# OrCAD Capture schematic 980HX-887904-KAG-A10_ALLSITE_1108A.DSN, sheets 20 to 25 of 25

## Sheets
20 T04.GROUP8.U4: size D
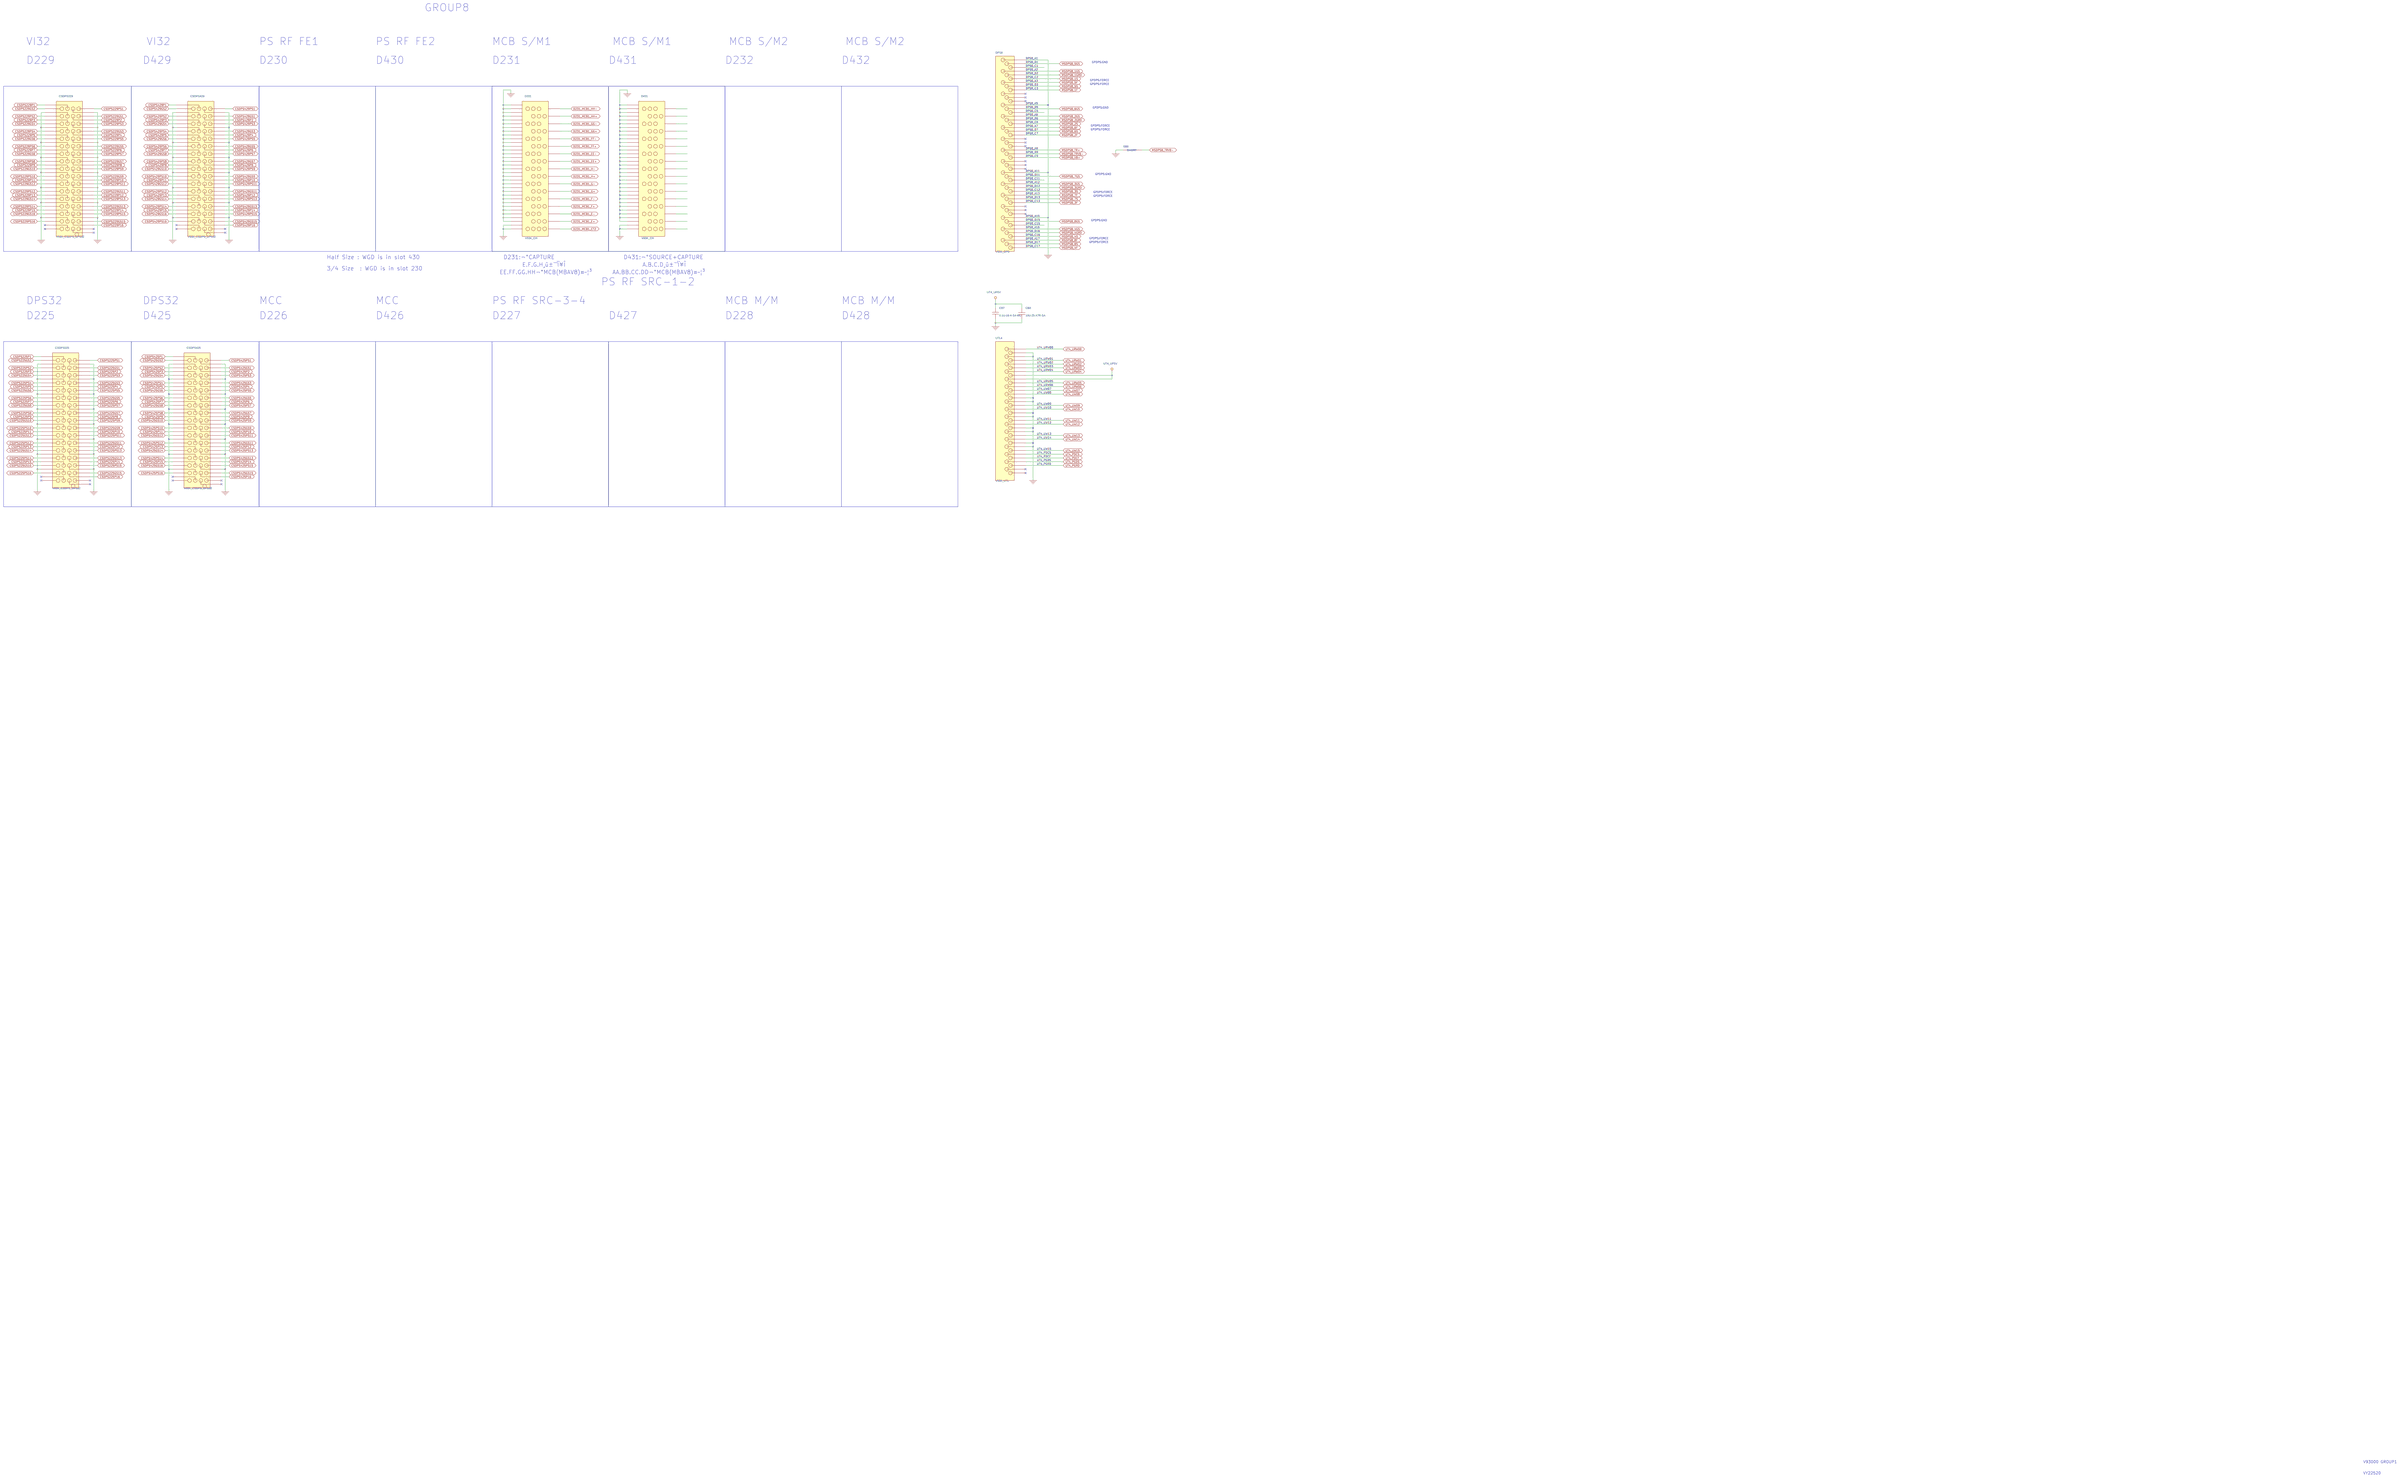
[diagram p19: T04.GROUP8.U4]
21 T05.GROUP4.U5: size D
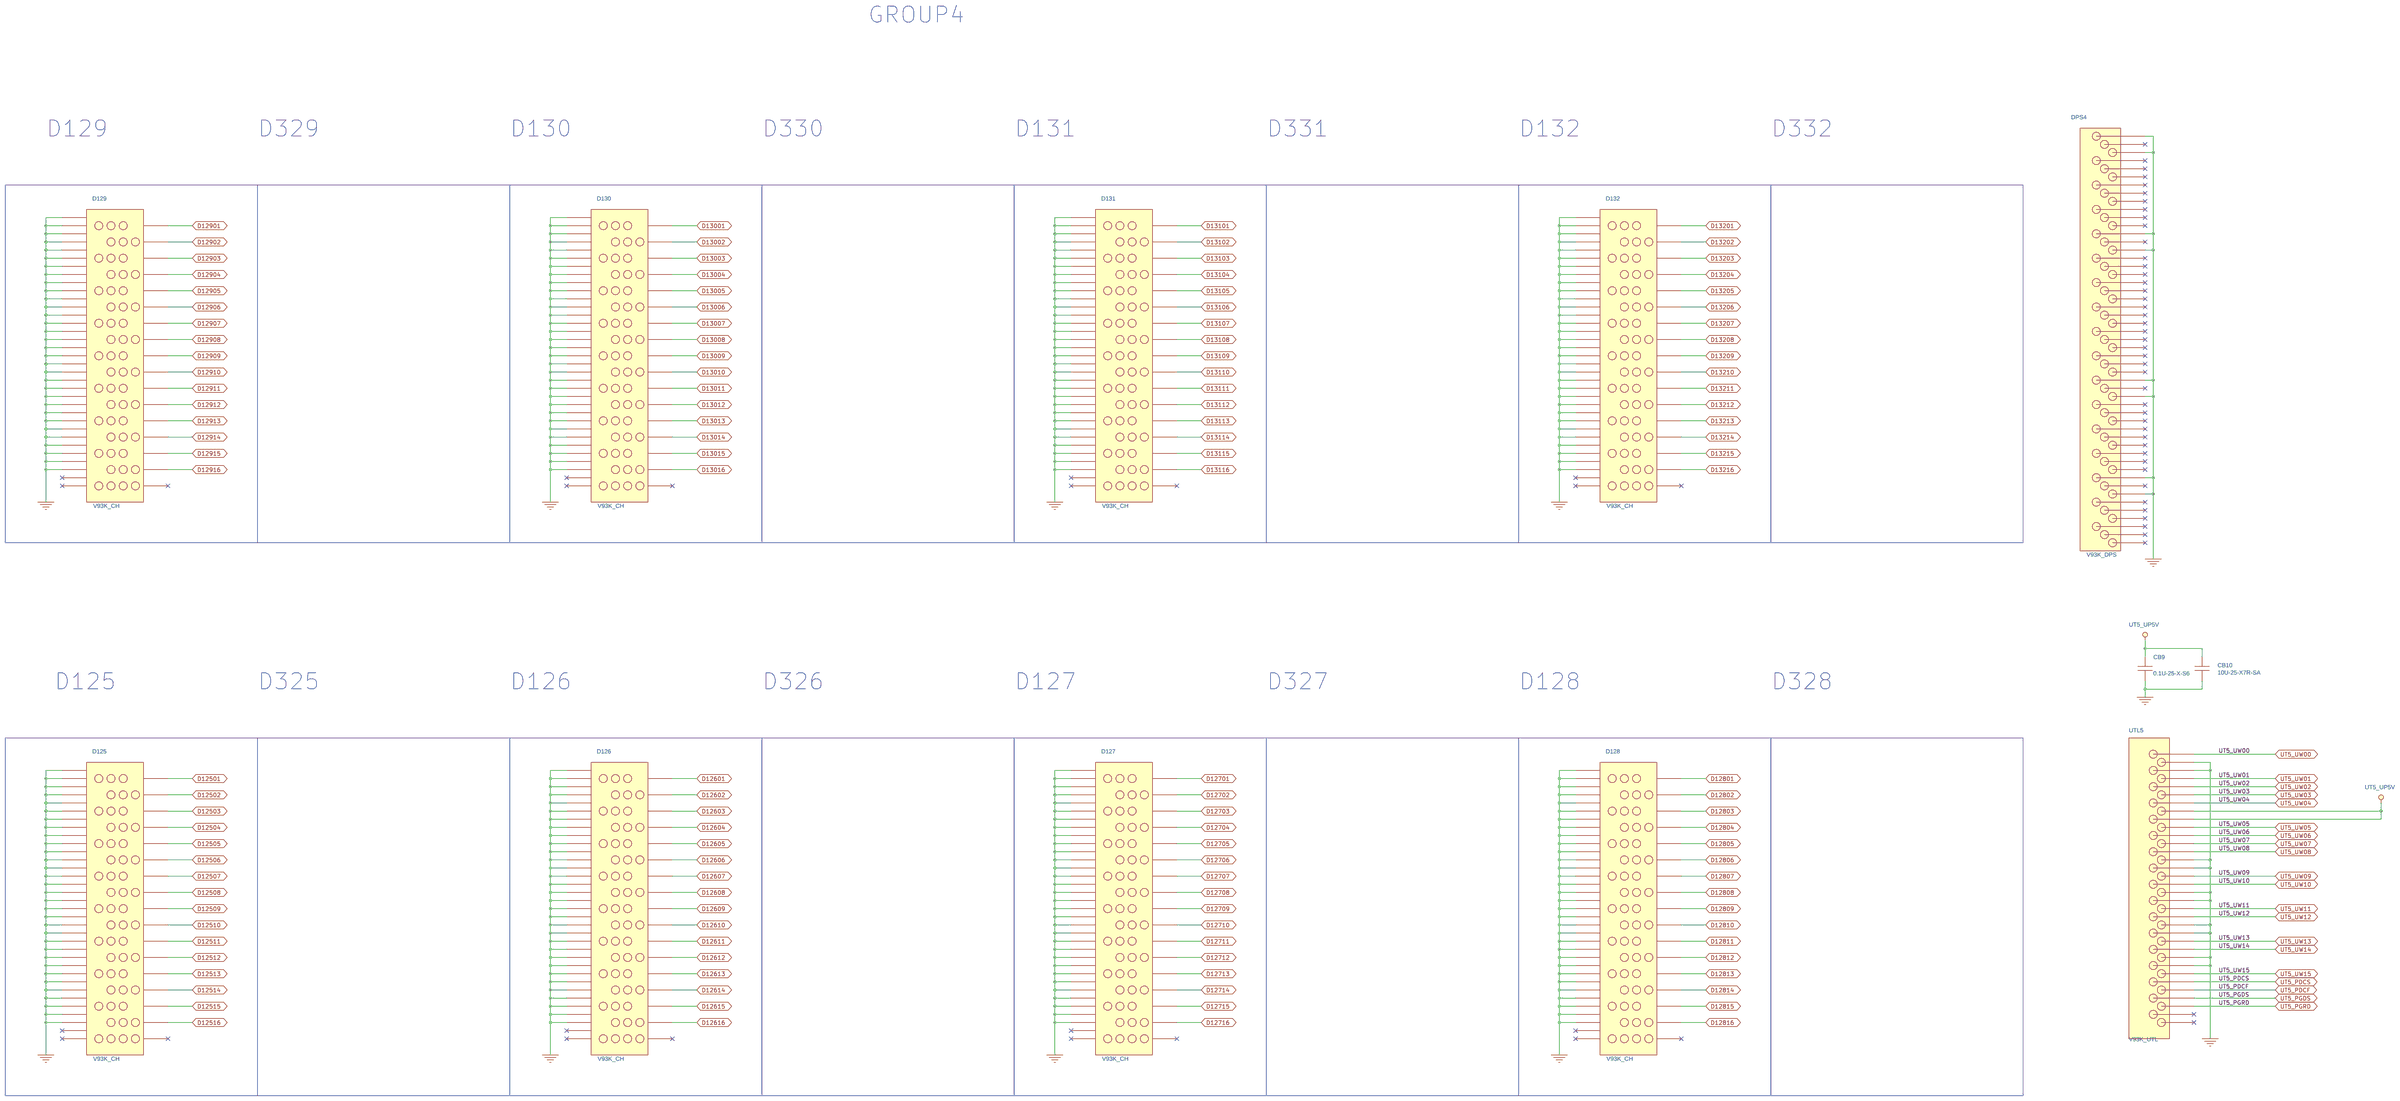
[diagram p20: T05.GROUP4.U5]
22 T06.GROUP5.U6: size D
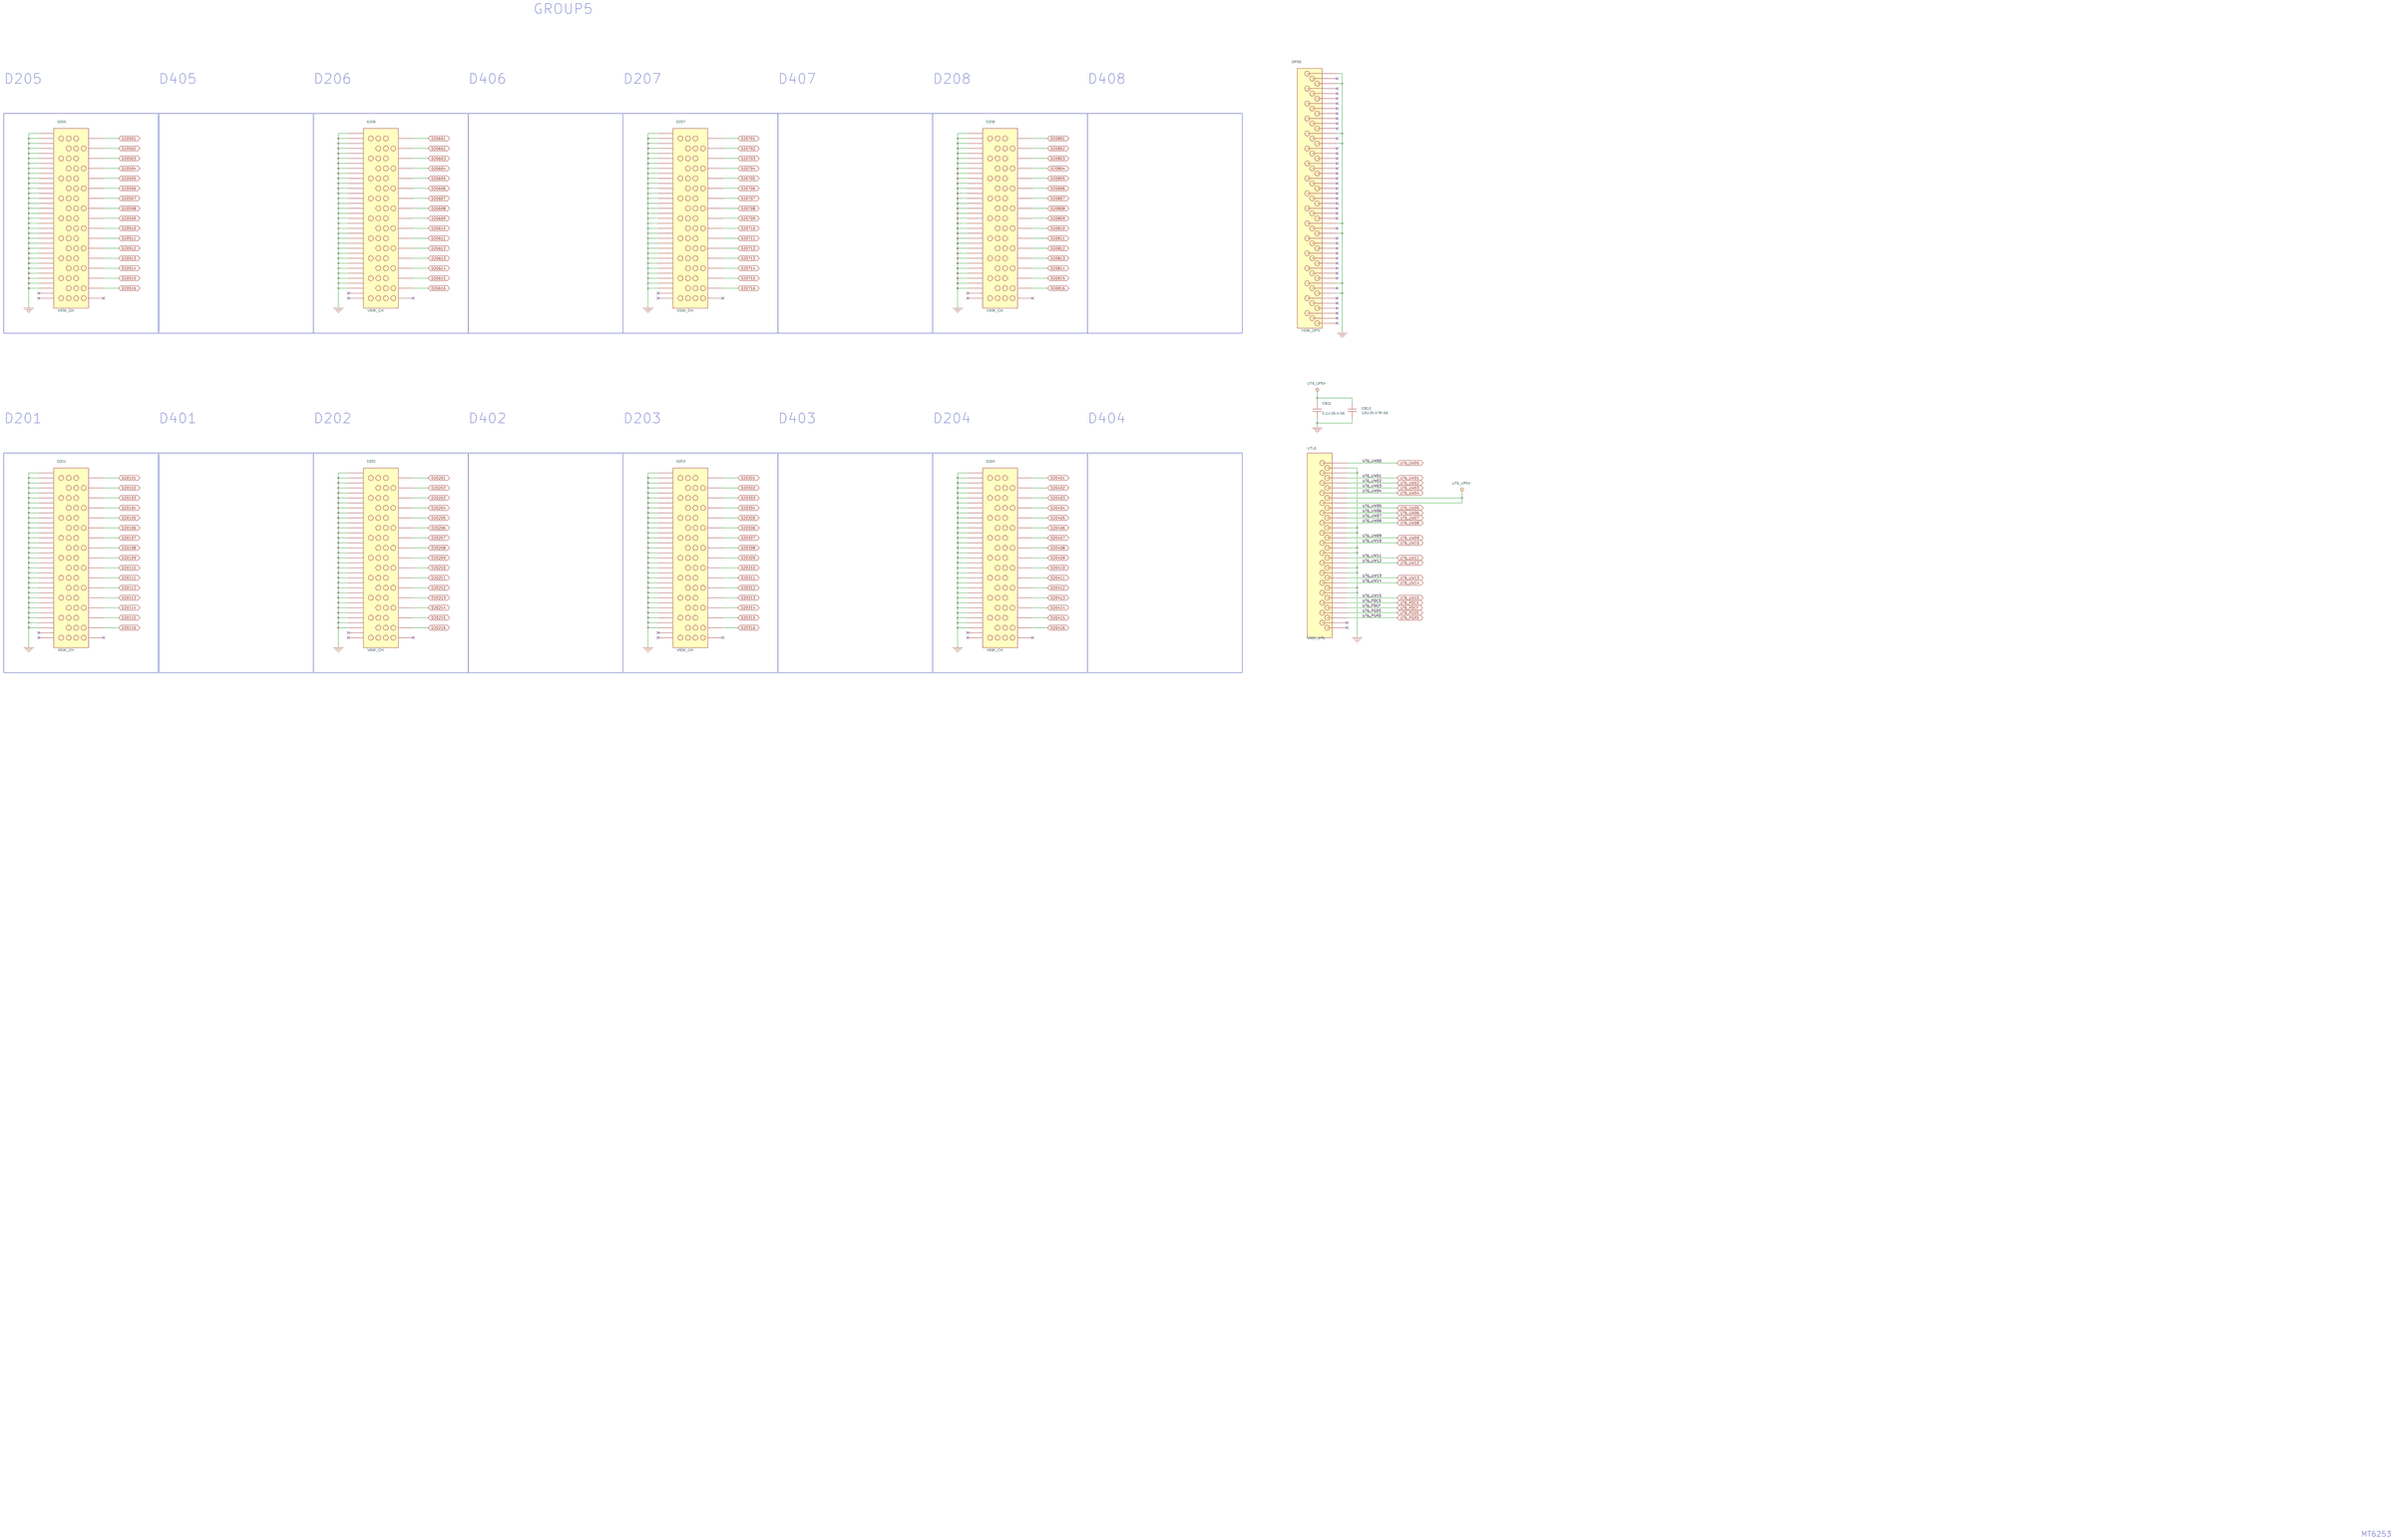
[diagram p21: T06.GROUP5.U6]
23 T07.GROUP6.U7: size D
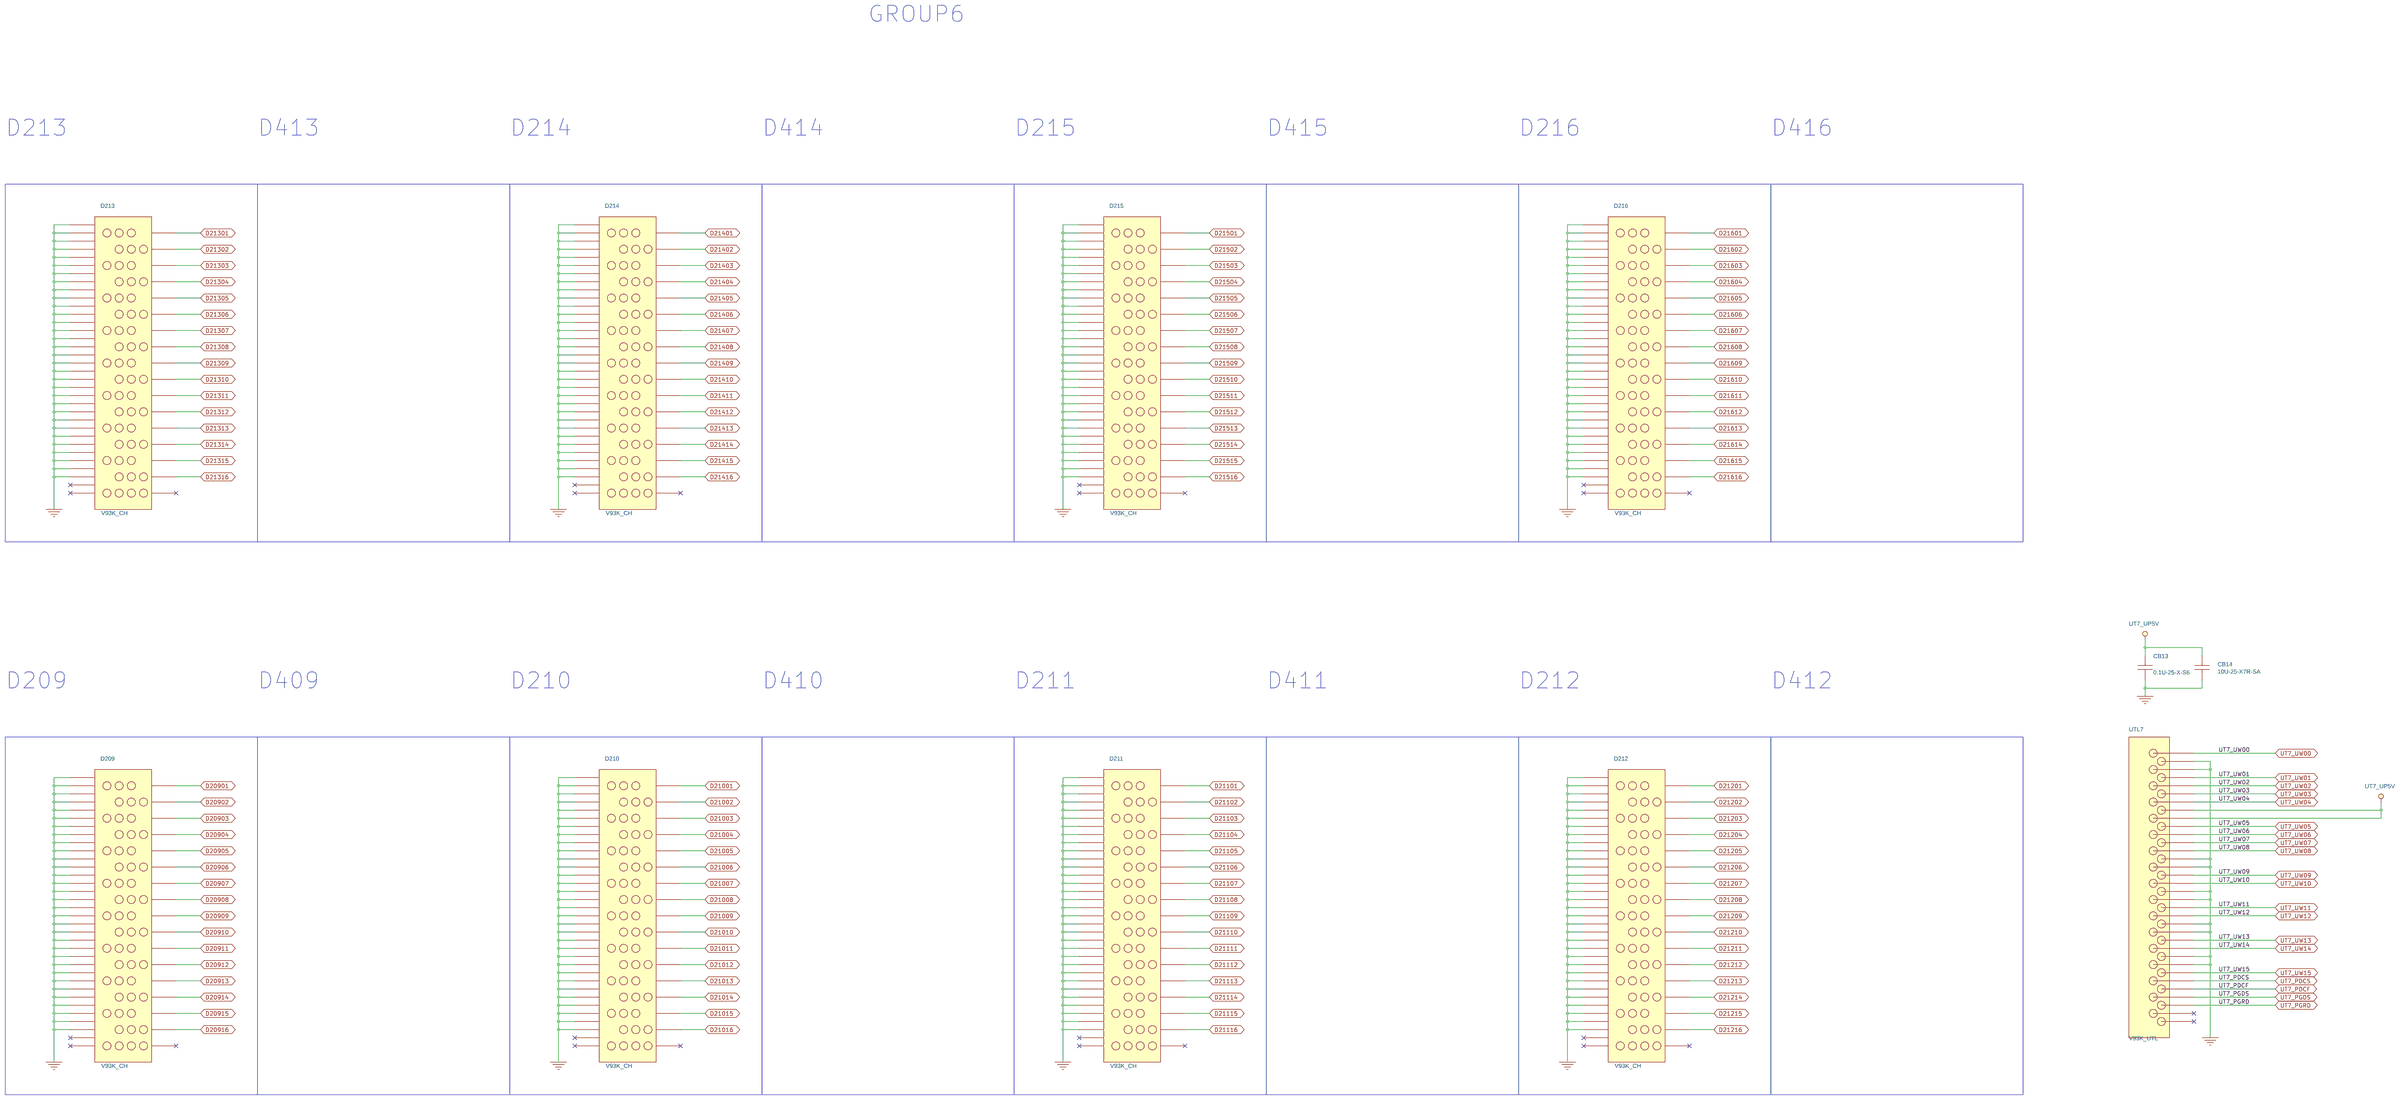
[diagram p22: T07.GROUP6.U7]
24 T08.GROUP7.U8: size D
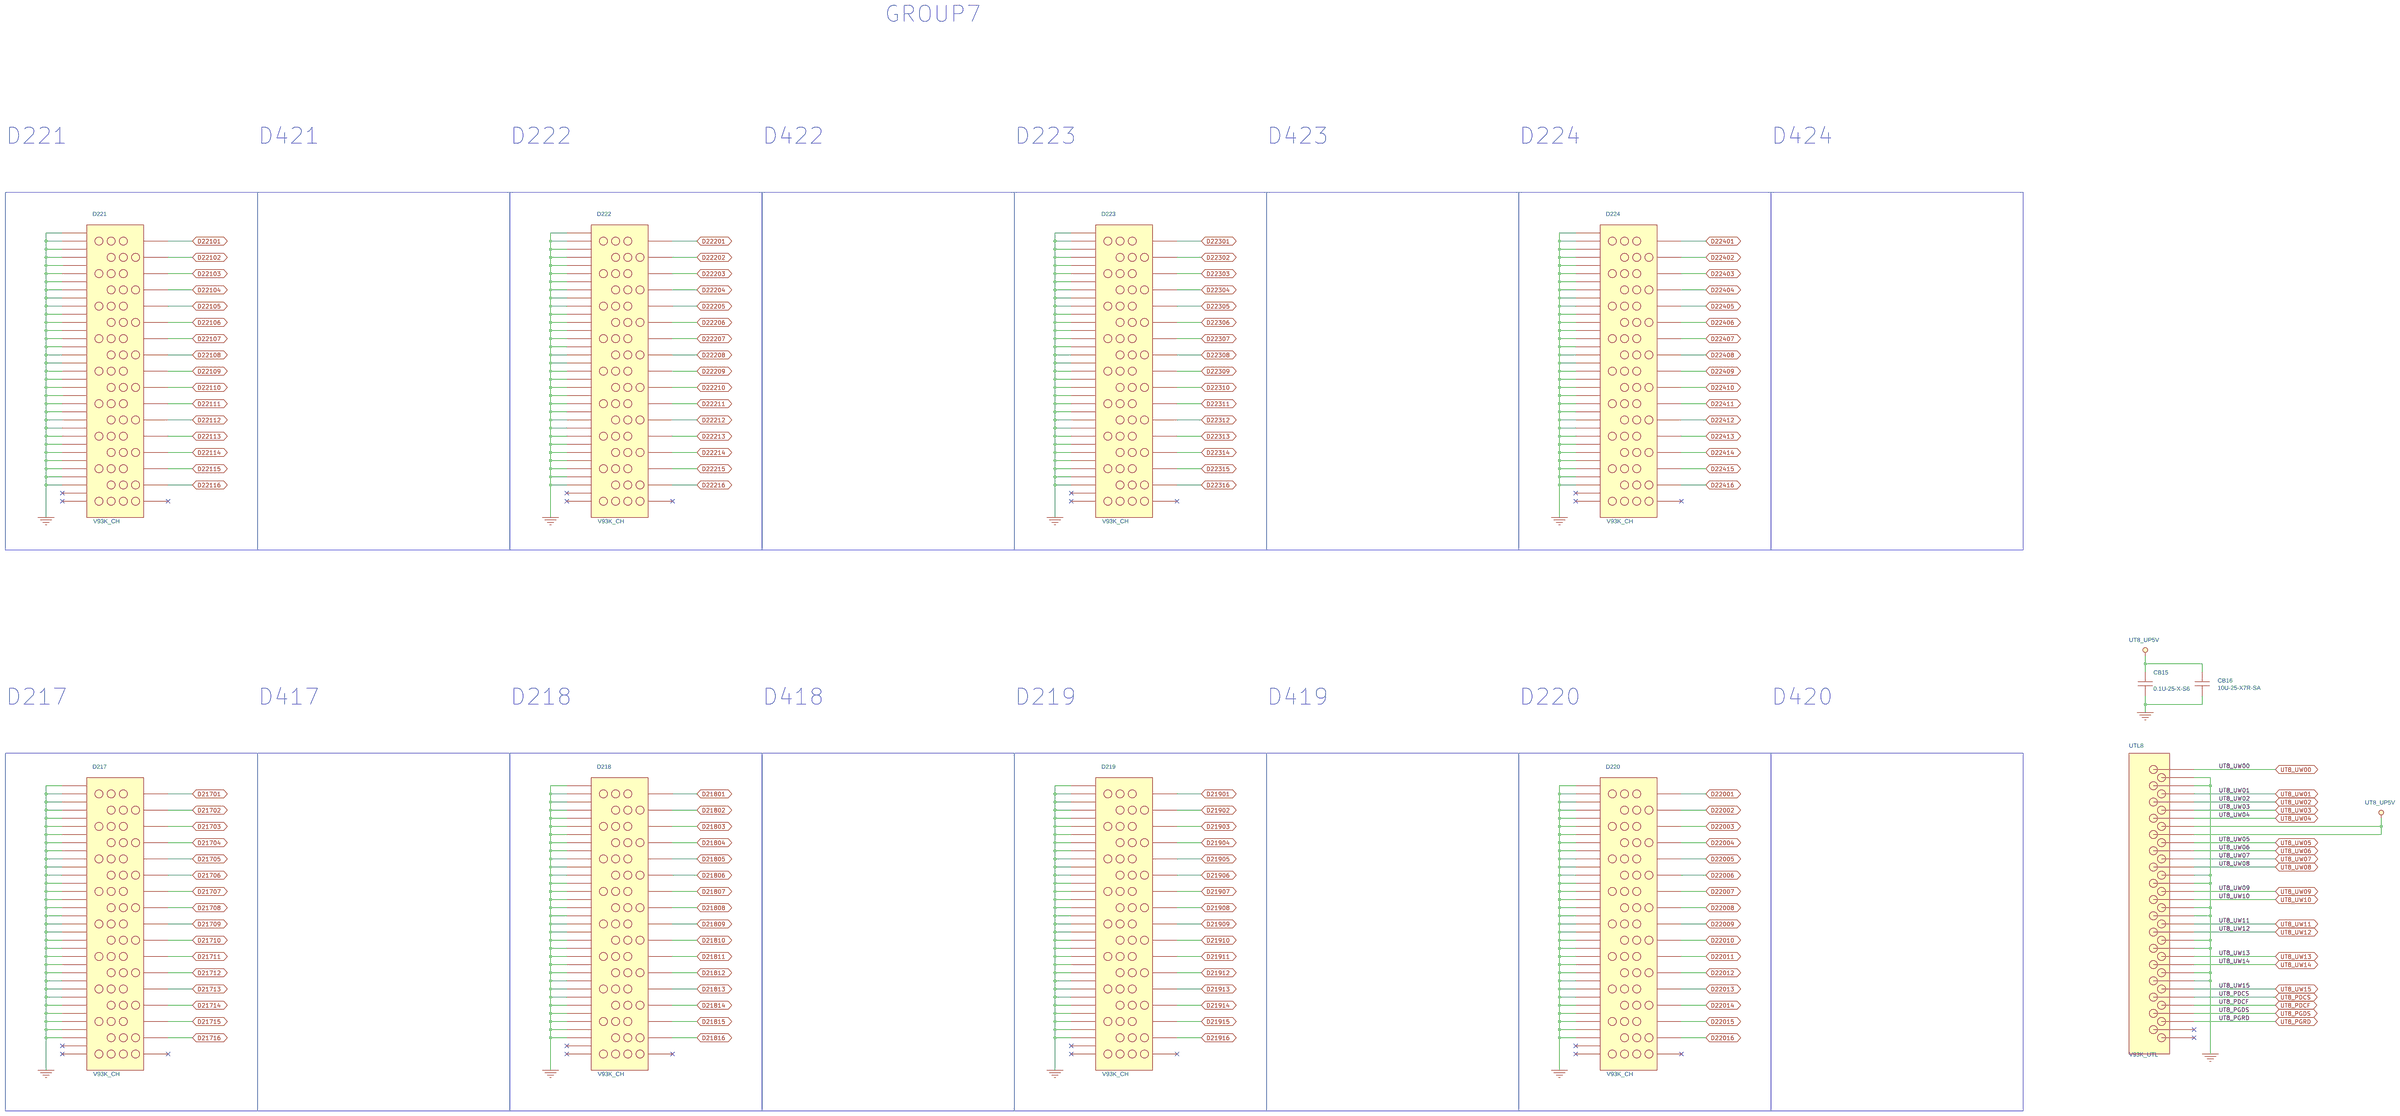
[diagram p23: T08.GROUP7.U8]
25 X01-ASSIGN RULE: size A3
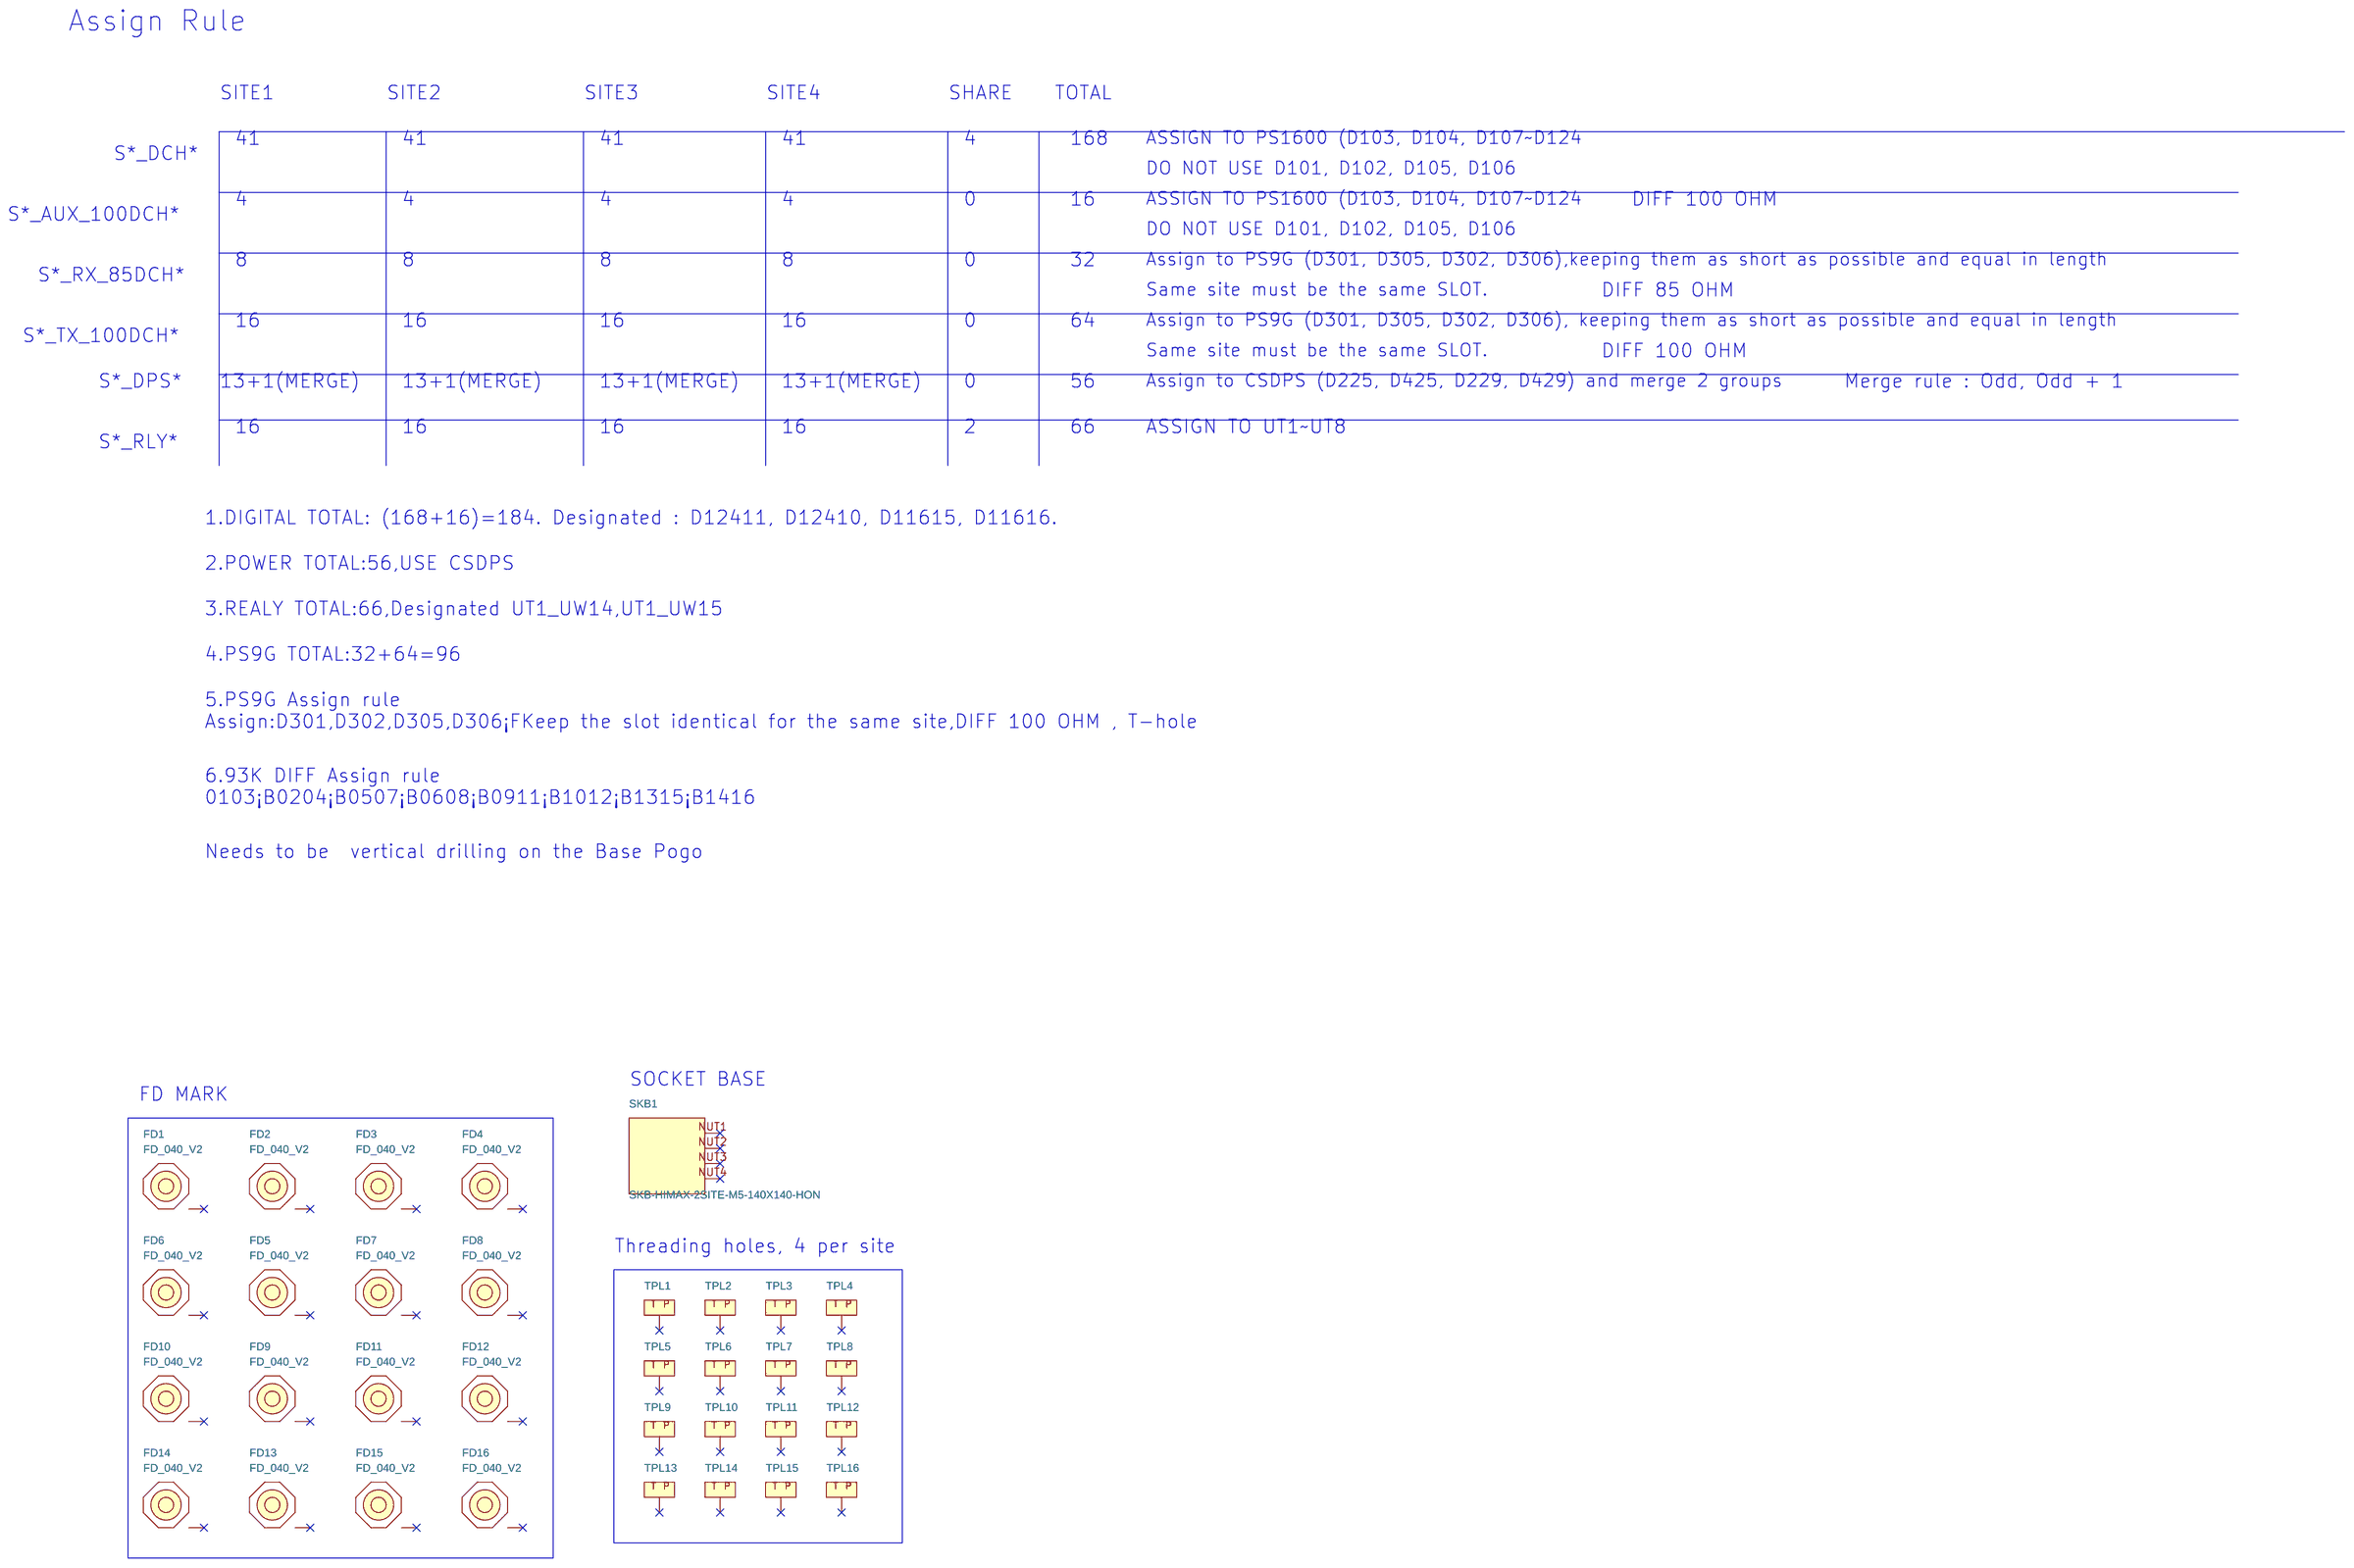
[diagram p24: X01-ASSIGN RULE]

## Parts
sheet T04.GROUP8.U4
CB7  0.1U-16-X-S4-MU  [C0402]
CB8  10U-25-X7R-SA  [C1206]
CSDPS225  V93K_CSDPS_DPS32  [PG_VG93K_PF_DPS32_G8D225]
CSDPS229  V93K_CSDPS_DPS32  [PG_VG93K_PF_DPS32_G8D229]
CSDPS425  V93K_CSDPS_DPS32  [PG_VG93K_PF_DPS32_G8D425]
CSDPS429  V93K_CSDPS_DPS32  [PG_VG93K_PF_DPS32_G8D429]
D231  V93K_CH  [PG_VG93K_F_G8D231]
D431  V93K_CH  [PG_VG93K_F_G8D431]
DPS8  V93K_DPS  [PG_VG93K_F_G8DPS8]
SB8  SHORT  [DEFAULT_SHORT_SMALL]
UTL4  V93K_UTL  [PG_VG93K_F_G8UTI4]
sheet T05.GROUP4.U5
CB9  0.1U-25-X-S6  [C0603]
CB10  10U-25-X7R-SA  [C1206]
D125  V93K_CH  [PG_VG93K_F_G4D125]
D126  V93K_CH  [PG_VG93K_F_G4D126]
D127  V93K_CH  [PG_VG93K_F_G4D127]
D128  V93K_CH  [PG_VG93K_F_G4D128]
D129  V93K_CH  [PG_VG93K_F_G4D129]
D130  V93K_CH  [PG_VG93K_F_G4D130]
D131  V93K_CH  [PG_VG93K_F_G4D131]
D132  V93K_CH  [PG_VG93K_F_G4D132]
DPS4  V93K_DPS  [PG_VG93K_F_G4DPS4]
UTL5  V93K_UTL  [PG_VG93K_F_G4UTI5]
sheet T06.GROUP5.U6
CB11  0.1U-25-X-S6  [C0603]
CB12  10U-25-X7R-SA  [C1206]
D201  V93K_CH  [PG_VG93K_F_G5D201]
D202  V93K_CH  [PG_VG93K_F_G5D202]
D203  V93K_CH  [PG_VG93K_F_G5D203]
D204  V93K_CH  [PG_VG93K_F_G5D204]
D205  V93K_CH  [PG_VG93K_F_G5D205]
D206  V93K_CH  [PG_VG93K_F_G5D206]
D207  V93K_CH  [PG_VG93K_F_G5D207]
D208  V93K_CH  [PG_VG93K_F_G5D208]
DPS5  V93K_DPS  [PG_VG93K_F_G5DPS5]
UTL6  V93K_UTL  [PG_VG93K_F_G5UTI6]
sheet T07.GROUP6.U7
CB13  0.1U-25-X-S6  [C0603]
CB14  10U-25-X7R-SA  [C1206]
D209  V93K_CH  [PG_VG93K_F_G6D209]
D210  V93K_CH  [PG_VG93K_F_G6D210]
D211  V93K_CH  [PG_VG93K_F_G6D211]
D212  V93K_CH  [PG_VG93K_F_G6D212]
D213  V93K_CH  [PG_VG93K_F_G6D213]
D214  V93K_CH  [PG_VG93K_F_G6D214]
D215  V93K_CH  [PG_VG93K_F_G6D215]
D216  V93K_CH  [PG_VG93K_F_G6D216]
UTL7  V93K_UTL  [PG_VG93K_F_G6UTI7]
sheet T08.GROUP7.U8
CB15  0.1U-25-X-S6  [C0603]
CB16  10U-25-X7R-SA  [C1206]
D217  V93K_CH  [PG_VG93K_F_G7D217]
D218  V93K_CH  [PG_VG93K_F_G7D218]
D219  V93K_CH  [PG_VG93K_F_G7D219]
D220  V93K_CH  [PG_VG93K_F_G7D220]
D221  V93K_CH  [PG_VG93K_F_G7D221]
D222  V93K_CH  [PG_VG93K_F_G7D222]
D223  V93K_CH  [PG_VG93K_F_G7D223]
D224  V93K_CH  [PG_VG93K_F_G7D224]
UTL8  V93K_UTL  [PG_VG93K_F_G7UTI8]
sheet X01-ASSIGN RULE
FD1  FD_040_V2  [FD_040_V2]
FD2  FD_040_V2  [FD_040_V2]
FD3  FD_040_V2  [FD_040_V2]
FD4  FD_040_V2  [FD_040_V2]
FD5  FD_040_V2  [FD_040_V2]
FD6  FD_040_V2  [FD_040_V2]
FD7  FD_040_V2  [FD_040_V2]
FD8  FD_040_V2  [FD_040_V2]
FD9  FD_040_V2  [FD_040_V2]
FD10  FD_040_V2  [FD_040_V2]
FD11  FD_040_V2  [FD_040_V2]
FD12  FD_040_V2  [FD_040_V2]
FD13  FD_040_V2  [FD_040_V2]
FD14  FD_040_V2  [FD_040_V2]
FD15  FD_040_V2  [FD_040_V2]
FD16  FD_040_V2  [FD_040_V2]
SKB1  SKB-HIMAX-2SITE-M5-140X140-HON  [SOCKETBASE_294X213_888003]
TPL1  TPL01  [TPL_040_014_TB]
TPL2  TPL01  [TPL_040_014_TB]
TPL3  TPL01  [TPL_040_014_TB]
TPL4  TPL01  [TPL_040_014_TB]
TPL5  TPL01  [TPL_040_014_TB]
TPL6  TPL01  [TPL_040_014_TB]
TPL7  TPL01  [TPL_040_014_TB]
TPL8  TPL01  [TPL_040_014_TB]
TPL9  TPL01  [TPL_040_014_TB]
TPL10  TPL01  [TPL_040_014_TB]
TPL11  TPL01  [TPL_040_014_TB]
TPL12  TPL01  [TPL_040_014_TB]
TPL13  TPL01  [TPL_040_014_TB]
TPL14  TPL01  [TPL_040_014_TB]
TPL15  TPL01  [TPL_040_014_TB]
TPL16  TPL01  [TPL_040_014_TB]

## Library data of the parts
CB7 = 0.1U-16-X-S4-MU
CB8 CB10 CB12 CB14 CB16 = 10U-25-X7R-SA
CSDPS225 CSDPS229 CSDPS425 CSDPS429 = V93K_CSDPS_DPS32
D125-D132 D201-D224 D231 D431 = V93K_CH
DPS4 DPS5 DPS8 = V93K_DPS
SB8 = SHORT
UTL4-UTL8 = V93K_UTL
CB9 CB11 CB13 CB15 = 0.1U-25-X-S6
FD1-FD16 = FD_040_V2
SKB1 = SKB-HIMAX-2SITE-M5-140X140-HON
TPL1-TPL16 = TPL01

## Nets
GND: CSDPS225.B2 CSDPS225.B4 CSDPS225.B6 CSDPS225.B8 CSDPS225.B10 CSDPS225.B12 CSDPS225.B14 CSDPS225.B16 CSDPS225.C1 CSDPS225.C3 CSDPS225.C5 CSDPS225.C7 CSDPS225.C9 CSDPS225.C11 CSDPS225.C13 CSDPS225.C15 CSDPS229.B2 CSDPS229.B4 CSDPS229.B6 CSDPS229.B8 CSDPS229.B10 CSDPS229.B12 CSDPS229.B14 CSDPS229.B16 CSDPS229.C1 CSDPS229.C3 CSDPS229.C5 CSDPS229.C7 CSDPS229.C9 CSDPS229.C11 CSDPS229.C13 CSDPS229.C15 CSDPS425.B2 CSDPS425.B4 CSDPS425.B6 CSDPS425.B8 CSDPS425.B10 CSDPS425.B12 CSDPS425.B14 CSDPS425.B16 CSDPS425.C1 CSDPS425.C3 CSDPS425.C5 CSDPS425.C7 CSDPS425.C9 CSDPS425.C11 CSDPS425.C13 CSDPS425.C15 CSDPS429.B2 CSDPS429.B4 CSDPS429.B6 CSDPS429.B8 CSDPS429.B10 CSDPS429.B12 CSDPS429.B14 CSDPS429.B16 CSDPS429.C1 CSDPS429.C3 CSDPS429.C5 CSDPS429.C7 CSDPS429.C9 CSDPS429.C11 CSDPS429.C13 CSDPS429.C15 D125.A1 D125.A2 D125.A3 D125.A4 D125.A5 D125.A6 D125.A7 D125.A8 D125.A9 D125.A10 D125.A11 D125.A12 D125.A13 D125.A14 D125.A15 D125.A16 D125.B1 D125.B2 D125.B3 D125.B4 D125.B5 D125.B6 D125.B7 D125.B8 D125.B9 D125.B10 D125.B11 D125.B12 D125.B13 D125.B14 D125.B15 D125.B16 D126.A1 D126.A2 D126.A3 D126.A4 D126.A5 D126.A6 D126.A7 D126.A8 D126.A9 D126.A10 D126.A11 D126.A12 D126.A13 D126.A14 D126.A15 D126.A16 D126.B1 D126.B2 D126.B3 D126.B4 D126.B5 D126.B6 D126.B7 D126.B8 D126.B9 D126.B10 D126.B11 D126.B12 D126.B13 D126.B14 D126.B15 D126.B16 D127.A1 D127.A2 D127.A3 D127.A4 D127.A5 D127.A6 D127.A7 D127.A8 D127.A9 D127.A10 D127.A11 D127.A12 D127.A13 D127.A14 D127.A15 D127.A16 D127.B1 D127.B2 D127.B3 D127.B4 D127.B5 D127.B6 D127.B7 D127.B8 D127.B9 D127.B10 D127.B11 D127.B12 D127.B13 D127.B14 D127.B15 D127.B16 D128.A1 D128.A2 D128.A3 D128.A4 D128.A5 D128.A6 D128.A7 D128.A8 D128.A9 D128.A10 D128.A11 D128.A12 D128.A13 D128.A14 D128.A15 D128.A16 D128.B1 D128.B2 D128.B3 D128.B4 D128.B5 D128.B6 D128.B7 D128.B8 D128.B9 D128.B10 D128.B11 D128.B12 D128.B13 D128.B14 D128.B15 D128.B16 D129.A1 D129.A2 D129.A3 D129.A4 D129.A5 D129.A6 D129.A7 D129.A8 D129.A9 D129.A10 D129.A11 D129.A12 D129.A13 D129.A14 D129.A15 D129.A16 D129.B1 D129.B2 D129.B3 D129.B4 D129.B5 D129.B6 D129.B7 D129.B8 D129.B9 D129.B10 D129.B11 D129.B12 D129.B13 D129.B14 D129.B15 D129.B16 D130.A1 D130.A2 D130.A3 D130.A4 D130.A5 D130.A6 D130.A7 D130.A8 D130.A9 D130.A10 D130.A11 D130.A12 D130.A13 D130.A14 D130.A15 D130.A16 D130.B1 D130.B2 D130.B3 D130.B4 D130.B5 D130.B6 D130.B7 D130.B8 D130.B9 D130.B10 D130.B11 D130.B12 D130.B13 D130.B14 D130.B15 D130.B16 D131.A1 D131.A2 D131.A3 D131.A4 D131.A5 D131.A6 D131.A7 D131.A8 D131.A9 D131.A10 D131.A11 D131.A12 D131.A13 D131.A14 D131.A15 D131.A16 D131.B1 D131.B2 D131.B3 D131.B4 D131.B5 D131.B6 D131.B7 D131.B8 D131.B9 D131.B10 D131.B11 D131.B12 D131.B13 D131.B14 D131.B15 D131.B16 D132.A1 D132.A2 D132.A3 D132.A4 D132.A5 D132.A6 D132.A7 D132.A8 D132.A9 D132.A10 D132.A11 D132.A12 D132.A13 D132.A14 D132.A15 D132.A16 D132.B1 D132.B2 D132.B3 D132.B4 D132.B5 D132.B6 D132.B7 D132.B8 D132.B9 D132.B10 D132.B11 D132.B12 D132.B13 D132.B14 D132.B15 D132.B16 D201.A1 D201.A2 D201.A3 D201.A4 D201.A5 D201.A6 D201.A7 D201.A8 D201.A9 D201.A10 D201.A11 D201.A12 D201.A13 D201.A14 D201.A15 D201.A16 D201.B1 D201.B2 D201.B3 D201.B4 D201.B5 D201.B6 D201.B7 D201.B8 D201.B9 D201.B10 D201.B11 D201.B12 D201.B13 D201.B14 D201.B15 D201.B16 D202.A1 D202.A2 D202.A3 D202.A4 D202.A5 D202.A6 D202.A7 D202.A8 D202.A9 D202.A10 D202.A11 D202.A12 D202.A13 D202.A14 D202.A15 D202.A16 D202.B1 D202.B2 D202.B3 D202.B4 D202.B5 D202.B6 D202.B7 D202.B8 D202.B9 D202.B10 D202.B11 D202.B12 D202.B13 D202.B14 D202.B15 D202.B16 D203.A1 D203.A2 D203.A3 D203.A4 D203.A5 D203.A6 D203.A7 D203.A8 D203.A9 D203.A10 D203.A11 D203.A12 D203.A13 D203.A14 D203.A15 D203.A16 D203.B1 D203.B2 D203.B3 D203.B4 D203.B5 D203.B6 D203.B7 D203.B8 D203.B9 D203.B10 D203.B11 D203.B12 D203.B13 D203.B14 D203.B15 D203.B16 D204.A1 D204.A2 D204.A3 D204.A4 D204.A5 D204.A6 D204.A7 D204.A8 D204.A9 D204.A10 D204.A11 D204.A12 D204.A13 D204.A14 D204.A15 D204.A16 D204.B1 D204.B2 D204.B3 D204.B4 D204.B5 D204.B6 D204.B7 D204.B8 D204.B9 D204.B10 D204.B11 D204.B12 D204.B13 D204.B14 D204.B15 D204.B16 D205.A1 D205.A2 D205.A3 D205.A4 D205.A5 D205.A6 D205.A7 D205.A8 D205.A9 D205.A10 D205.A11 D205.A12 D205.A13 D205.A14 D205.A15 D205.A16 D205.B1 D205.B2 D205.B3 D205.B4 D205.B5 D205.B6 D205.B7 D205.B8 D205.B9 D205.B10 D205.B11 D205.B12 D205.B13 D205.B14 D205.B15 D205.B16 D206.A1 D206.A2 D206.A3 D206.A4 D206.A5 D206.A6 D206.A7 D206.A8 D206.A9 D206.A10 D206.A11 D206.A12 D206.A13 D206.A14 D206.A15 D206.A16 D206.B1 D206.B2 D206.B3 D206.B4 D206.B5 D206.B6 D206.B7 D206.B8 D206.B9 D206.B10 D206.B11 D206.B12 D206.B13 D206.B14 D206.B15 D206.B16 D207.A1 D207.A2 D207.A3 D207.A4 D207.A5 D207.A6 D207.A7 D207.A8 D207.A9 D207.A10 D207.A11 D207.A12 D207.A13 D207.A14 D207.A15 D207.A16 D207.B1 D207.B2 D207.B3 D207.B4 D207.B5 D207.B6 D207.B7 D207.B8 D207.B9 D207.B10 D207.B11 D207.B12 D207.B13 D207.B14 D207.B15 D207.B16 D208.A1 D208.A2 D208.A3 D208.A4 D208.A5 D208.A6 D208.A7 D208.A8 D208.A9 D208.A10 D208.A11 D208.A12 D208.A13 D208.A14 D208.A15 D208.A16 D208.B1 D208.B2 D208.B3 D208.B4 D208.B5 D208.B6 D208.B7 D208.B8 D208.B9 D208.B10 D208.B11 D208.B12 D208.B13 D208.B14 D208.B15 D208.B16 D209.A1 D209.A2 D209.A3 D209.A4 D209.A5 D209.A6 D209.A7 D209.A8 D209.A9 D209.A10 D209.A11 D209.A12 D209.A13 D209.A14 D209.A15 D209.A16 D209.B1 D209.B2 D209.B3 D209.B4 D209.B5 D209.B6 D209.B7 D209.B8 D209.B9 D209.B10 D209.B11 D209.B12 D209.B13 D209.B14 D209.B15 D209.B16 D210.A1 D210.A2 D210.A3 D210.A4 D210.A5 D210.A6 D210.A7 D210.A8 D210.A9 D210.A10 D210.A11 D210.A12 D210.A13 D210.A14 D210.A15 D210.A16 D210.B1 D210.B2 D210.B3 D210.B4 D210.B5 D210.B6 D210.B7 D210.B8 D210.B9 D210.B10 D210.B11 D210.B12 D210.B13 D210.B14 D210.B15 D210.B16 D211.A1 D211.A2 D211.A3 D211.A4 D211.A5 D211.A6 D211.A7 D211.A8 D211.A9 D211.A10 D211.A11 D211.A12 D211.A13 D211.A14 D211.A15 D211.A16 D211.B1 D211.B2 D211.B3 D211.B4 D211.B5 D211.B6 D211.B7 D211.B8 D211.B9 D211.B10 D211.B11 D211.B12 D211.B13 D211.B14 D211.B15 D211.B16 D212.A1 D212.A2 D212.A3 D212.A4 D212.A5 D212.A6 D212.A7 D212.A8 D212.A9 D212.A10 D212.A11 D212.A12 D212.A13 D212.A14 D212.A15 D212.A16 D212.B1 D212.B2 D212.B3 D212.B4 D212.B5 D212.B6 D212.B7 D212.B8 D212.B9 D212.B10 D212.B11 D212.B12 D212.B13 D212.B14 D212.B15 D212.B16 D213.A1 D213.A2 D213.A3 D213.A4 D213.A5 D213.A6 D213.A7 D213.A8 D213.A9 D213.A10 D213.A11 D213.A12 D213.A13 D213.A14 D213.A15 D213.A16 D213.B1 D213.B2 D213.B3 D213.B4 D213.B5 D213.B6 D213.B7 D213.B8 D213.B9 D213.B10 D213.B11 D213.B12 D213.B13 D213.B14 D213.B15 D213.B16 D214.A1 D214.A2 D214.A3 D214.A4 D214.A5 D214.A6 D214.A7 D214.A8 D214.A9 D214.A10 D214.A11 D214.A12 D214.A13 D214.A14 D214.A15 D214.A16 D214.B1 D214.B2 D214.B3 D214.B4 D214.B5 D214.B6 D214.B7 D214.B8 D214.B9 D214.B10 D214.B11 D214.B12 D214.B13 D214.B14 D214.B15 D214.B16 D215.A1 D215.A2 D215.A3 D215.A4 D215.A5 D215.A6 D215.A7 D215.A8 D215.A9 D215.A10 D215.A11 D215.A12 D215.A13 D215.A14 D215.A15 D215.A16 D215.B1 D215.B2 D215.B3 D215.B4 D215.B5 D215.B6 D215.B7 D215.B8 D215.B9 D215.B10 D215.B11 D215.B12 D215.B13 D215.B14 D215.B15 D215.B16 D216.A1 D216.A2 D216.A3 D216.A4 D216.A5 D216.A6 D216.A7 D216.A8 D216.A9 D216.A10 D216.A11 D216.A12 D216.A13 D216.A14 D216.A15 D216.A16 D216.B1 D216.B2 D216.B3 D216.B4 D216.B5 D216.B6 D216.B7 D216.B8 D216.B9 D216.B10 D216.B11 D216.B12 D216.B13 D216.B14 D216.B15 D216.B16 D217.A1 D217.A2 D217.A3 D217.A4 D217.A5 D217.A6 D217.A7 D217.A8 D217.A9 D217.A10 D217.A11 D217.A12 D217.A13 D217.A14 D217.A15 D217.A16 D217.B1 D217.B2 D217.B3 D217.B4 D217.B5 D217.B6 D217.B7 D217.B8 D217.B9 D217.B10 D217.B11 D217.B12 D217.B13 D217.B14 D217.B15 D217.B16 D218.A1 D218.A2 D218.A3 D218.A4 D218.A5 D218.A6 D218.A7 D218.A8 D218.A9 D218.A10 D218.A11 D218.A12 D218.A13 D218.A14 D218.A15 D218.A16 D218.B1 D218.B2 D218.B3 D218.B4 D218.B5 D218.B6 D218.B7 D218.B8 D218.B9 D218.B10 D218.B11 D218.B12 D218.B13 D218.B14 D218.B15 D218.B16 D219.A1 D219.A2 D219.A3 D219.A4 D219.A5 D219.A6 D219.A7 D219.A8 D219.A9 D219.A10 D219.A11 D219.A12 D219.A13 D219.A14 D219.A15 D219.A16 D219.B1 D219.B2 D219.B3 D219.B4 D219.B5 D219.B6 D219.B7 D219.B8 D219.B9 D219.B10 D219.B11 D219.B12 D219.B13 D219.B14 D219.B15 D219.B16 D220.A1 D220.A2 D220.A3 D220.A4 D220.A5 D220.A6 D220.A7 D220.A8 D220.A9 D220.A10 D220.A11 D220.A12 D220.A13 D220.A14 D220.A15 D220.A16 D220.B1 D220.B2 D220.B3 D220.B4 D220.B5 D220.B6 D220.B7 D220.B8 D220.B9 D220.B10 D220.B11 D220.B12 D220.B13 D220.B14 D220.B15 D220.B16 D221.A1 D221.A2 D221.A3 D221.A4 D221.A5 D221.A6 D221.A7 D221.A8 D221.A9 D221.A10 D221.A11 D221.A12 D221.A13 D221.A14 D221.A15 D221.A16 D221.B1 D221.B2 D221.B3 D221.B4 D221.B5 D221.B6 D221.B7 D221.B8 D221.B9 D221.B10 D221.B11 D221.B12 D221.B13 D221.B14 D221.B15 D221.B16 D222.A1 D222.A2 D222.A3 D222.A4 D222.A5 D222.A6 D222.A7 D222.A8 D222.A9 D222.A10 D222.A11 D222.A12 D222.A13 D222.A14 D222.A15 D222.A16 D222.B1 D222.B2 D222.B3 D222.B4 D222.B5 D222.B6 D222.B7 D222.B8 D222.B9 D222.B10 D222.B11 D222.B12 D222.B13 D222.B14 D222.B15 D222.B16 D223.A1 D223.A2 D223.A3 D223.A4 D223.A5 D223.A6 D223.A7 D223.A8 D223.A9 D223.A10 D223.A11 D223.A12 D223.A13 D223.A14 D223.A15 D223.A16 D223.B1 D223.B2 D223.B3 D223.B4 D223.B5 D223.B6 D223.B7 D223.B8 D223.B9 D223.B10 D223.B11 D223.B12 D223.B13 D223.B14 D223.B15 D223.B16 D224.A1 D224.A2 D224.A3 D224.A4 D224.A5 D224.A6 D224.A7 D224.A8 D224.A9 D224.A10 D224.A11 D224.A12 D224.A13 D224.A14 D224.A15 D224.A16 D224.B1 D224.B2 D224.B3 D224.B4 D224.B5 D224.B6 D224.B7 D224.B8 D224.B9 D224.B10 D224.B11 D224.B12 D224.B13 D224.B14 D224.B15 D224.B16 D231.A1 D231.A2 D231.A3 D231.A4 D231.A5 D231.A6 D231.A7 D231.A8 D231.A9 D231.A10 D231.A11 D231.A12 D231.A13 D231.A14 D231.A15 D231.A16 D231.A17 D231.B1 D231.B2 D231.B3 D231.B4 D231.B5 D231.B6 D231.B7 D231.B8 D231.B9 D231.B10 D231.B11 D231.B12 D231.B13 D231.B14 D231.B15 D231.B16 D231.B17 D431.A1 D431.A2 D431.A3 D431.A4 D431.A5 D431.A6 D431.A7 D431.A8 D431.A9 D431.A10 D431.A11 D431.A12 D431.A13 D431.A14 D431.A15 D431.A16 D431.A17 D431.B1 D431.B2 D431.B3 D431.B4 D431.B5 D431.B6 D431.B7 D431.B8 D431.B9 D431.B10 D431.B11 D431.B12 D431.B13 D431.B14 D431.B15 D431.B16 D431.B17 DPS4.A01 DPS4.A05 DPS4.A11 DPS4.A15 DPS4.C01 DPS4.C05 DPS4.C11 DPS4.C15 DPS5.A01 DPS5.A05 DPS5.A11 DPS5.A15 DPS5.C01 DPS5.C05 DPS5.C11 DPS5.C15 DPS8.A01 DPS8.A05 DPS8.A11 DPS8.A15 SB8.1 ; also on sheet 1 2 3 4 5 6 7 8 9 12 13 14 15 16 17 18 19
CSDPS225GS1: CSDPS225.D2
CSDPS225GS2: CSDPS225.A1
CSDPS225GS3: CSDPS225.D4
CSDPS225GS4: CSDPS225.A3
CSDPS225GS5: CSDPS225.D6
CSDPS225GS6: CSDPS225.A5
CSDPS225GS7: CSDPS225.D8
CSDPS225GS8: CSDPS225.A7
CSDPS225GS9: CSDPS225.D10
CSDPS225GS10: CSDPS225.A9
CSDPS225GS11: CSDPS225.D12
CSDPS225GS12: CSDPS225.A11
CSDPS225GS13: CSDPS225.D14
CSDPS225GS14: CSDPS225.A13
CSDPS225GS15: CSDPS225.D16
CSDPS225GS16: CSDPS225.A15
CSDPS225P1: CSDPS225.B1
CSDPS225P2: CSDPS225.C2
CSDPS225P3: CSDPS225.B3
CSDPS225P4: CSDPS225.C4
CSDPS225P5: CSDPS225.B5
CSDPS225P6: CSDPS225.C6
CSDPS225P7: CSDPS225.B7
CSDPS225P8: CSDPS225.C8
CSDPS225P9: CSDPS225.B9
CSDPS225P10: CSDPS225.C10
CSDPS225P11: CSDPS225.B11
CSDPS225P12: CSDPS225.C12
CSDPS225P13: CSDPS225.B13
CSDPS225P14: CSDPS225.C14
CSDPS225P15: CSDPS225.B15
CSDPS225P16: CSDPS225.C16
CSDPS225PS1: CSDPS225.D1
CSDPS225PS2: CSDPS225.A2
CSDPS225PS3: CSDPS225.D3
CSDPS225PS4: CSDPS225.A4
CSDPS225PS5: CSDPS225.D5
CSDPS225PS6: CSDPS225.A6
CSDPS225PS7: CSDPS225.D7
CSDPS225PS8: CSDPS225.A8
CSDPS225PS9: CSDPS225.D9
CSDPS225PS10: CSDPS225.A10
CSDPS225PS11: CSDPS225.D11
CSDPS225PS12: CSDPS225.A12
CSDPS225PS13: CSDPS225.D13
CSDPS225PS14: CSDPS225.A14
CSDPS225PS15: CSDPS225.D15
CSDPS225PS16: CSDPS225.A16
CSDPS229GS1: CSDPS229.D2
CSDPS229GS2: CSDPS229.A1
CSDPS229GS3: CSDPS229.D4
CSDPS229GS4: CSDPS229.A3
CSDPS229GS5: CSDPS229.D6
CSDPS229GS6: CSDPS229.A5
CSDPS229GS7: CSDPS229.D8
CSDPS229GS8: CSDPS229.A7
CSDPS229GS9: CSDPS229.D10
CSDPS229GS10: CSDPS229.A9
CSDPS229GS11: CSDPS229.D12
CSDPS229GS12: CSDPS229.A11
CSDPS229GS13: CSDPS229.D14
CSDPS229GS14: CSDPS229.A13
CSDPS229GS15: CSDPS229.D16
CSDPS229GS16: CSDPS229.A15
CSDPS229P1: CSDPS229.B1
CSDPS229P2: CSDPS229.C2
CSDPS229P3: CSDPS229.B3
CSDPS229P4: CSDPS229.C4
CSDPS229P5: CSDPS229.B5
CSDPS229P6: CSDPS229.C6
CSDPS229P7: CSDPS229.B7
CSDPS229P8: CSDPS229.C8
CSDPS229P9: CSDPS229.B9
CSDPS229P10: CSDPS229.C10
CSDPS229P11: CSDPS229.B11
CSDPS229P12: CSDPS229.C12
CSDPS229P13: CSDPS229.B13
CSDPS229P14: CSDPS229.C14
CSDPS229P15: CSDPS229.B15
CSDPS229P16: CSDPS229.C16
CSDPS229PS1: CSDPS229.D1
CSDPS229PS2: CSDPS229.A2
CSDPS229PS3: CSDPS229.D3
CSDPS229PS4: CSDPS229.A4
CSDPS229PS5: CSDPS229.D5
CSDPS229PS6: CSDPS229.A6
CSDPS229PS7: CSDPS229.D7
CSDPS229PS8: CSDPS229.A8
CSDPS229PS9: CSDPS229.D9
CSDPS229PS10: CSDPS229.A10
CSDPS229PS11: CSDPS229.D11
CSDPS229PS12: CSDPS229.A12
CSDPS229PS13: CSDPS229.D13
CSDPS229PS14: CSDPS229.A14
CSDPS229PS15: CSDPS229.D15
CSDPS229PS16: CSDPS229.A16
CSDPS425GS1: CSDPS425.D2
CSDPS425GS2: CSDPS425.A1
CSDPS425GS3: CSDPS425.D4
CSDPS425GS4: CSDPS425.A3
CSDPS425GS5: CSDPS425.D6
CSDPS425GS6: CSDPS425.A5
CSDPS425GS7: CSDPS425.D8
CSDPS425GS8: CSDPS425.A7
CSDPS425GS9: CSDPS425.D10
CSDPS425GS10: CSDPS425.A9
CSDPS425GS11: CSDPS425.D12
CSDPS425GS12: CSDPS425.A11
CSDPS425GS13: CSDPS425.D14
CSDPS425GS14: CSDPS425.A13
CSDPS425GS15: CSDPS425.D16
CSDPS425GS16: CSDPS425.A15
CSDPS425P1: CSDPS425.B1
CSDPS425P2: CSDPS425.C2
CSDPS425P3: CSDPS425.B3
CSDPS425P4: CSDPS425.C4
CSDPS425P5: CSDPS425.B5
CSDPS425P6: CSDPS425.C6
CSDPS425P7: CSDPS425.B7
CSDPS425P8: CSDPS425.C8
CSDPS425P9: CSDPS425.B9
CSDPS425P10: CSDPS425.C10
CSDPS425P11: CSDPS425.B11
CSDPS425P12: CSDPS425.C12
CSDPS425P13: CSDPS425.B13
CSDPS425P14: CSDPS425.C14
CSDPS425P15: CSDPS425.B15
CSDPS425P16: CSDPS425.C16
CSDPS425PS1: CSDPS425.D1
CSDPS425PS2: CSDPS425.A2
CSDPS425PS3: CSDPS425.D3
CSDPS425PS4: CSDPS425.A4
CSDPS425PS5: CSDPS425.D5
CSDPS425PS6: CSDPS425.A6
CSDPS425PS7: CSDPS425.D7
CSDPS425PS8: CSDPS425.A8
CSDPS425PS9: CSDPS425.D9
CSDPS425PS10: CSDPS425.A10
CSDPS425PS11: CSDPS425.D11
CSDPS425PS12: CSDPS425.A12
CSDPS425PS13: CSDPS425.D13
CSDPS425PS14: CSDPS425.A14
CSDPS425PS15: CSDPS425.D15
CSDPS425PS16: CSDPS425.A16
CSDPS429GS1: CSDPS429.D2
CSDPS429GS2: CSDPS429.A1
CSDPS429GS3: CSDPS429.D4
CSDPS429GS4: CSDPS429.A3
CSDPS429GS5: CSDPS429.D6
CSDPS429GS6: CSDPS429.A5
CSDPS429GS7: CSDPS429.D8
CSDPS429GS8: CSDPS429.A7
CSDPS429GS9: CSDPS429.D10
CSDPS429GS10: CSDPS429.A9
CSDPS429GS11: CSDPS429.D12
CSDPS429GS12: CSDPS429.A11
CSDPS429GS13: CSDPS429.D14
CSDPS429GS14: CSDPS429.A13
CSDPS429GS15: CSDPS429.D16
CSDPS429GS16: CSDPS429.A15
CSDPS429P1: CSDPS429.B1
CSDPS429P2: CSDPS429.C2
CSDPS429P3: CSDPS429.B3
CSDPS429P4: CSDPS429.C4
CSDPS429P5: CSDPS429.B5
CSDPS429P6: CSDPS429.C6
CSDPS429P7: CSDPS429.B7
CSDPS429P8: CSDPS429.C8
CSDPS429P9: CSDPS429.B9
CSDPS429P10: CSDPS429.C10
CSDPS429P11: CSDPS429.B11
CSDPS429P12: CSDPS429.C12
CSDPS429P13: CSDPS429.B13
CSDPS429P14: CSDPS429.C14
CSDPS429P15: CSDPS429.B15
CSDPS429P16: CSDPS429.C16
CSDPS429PS1: CSDPS429.D1
CSDPS429PS2: CSDPS429.A2
CSDPS429PS3: CSDPS429.D3
CSDPS429PS4: CSDPS429.A4
CSDPS429PS5: CSDPS429.D5
CSDPS429PS6: CSDPS429.A6
CSDPS429PS7: CSDPS429.D7
CSDPS429PS8: CSDPS429.A8
CSDPS429PS9: CSDPS429.D9
CSDPS429PS10: CSDPS429.A10
CSDPS429PS11: CSDPS429.D11
CSDPS429PS12: CSDPS429.A12
CSDPS429PS13: CSDPS429.D13
CSDPS429PS14: CSDPS429.A14
CSDPS429PS15: CSDPS429.D15
CSDPS429PS16: CSDPS429.A16
D231_MCB1_E+: D231.16
D231_MCB1_E-: D231.15
D231_MCB1_EE+: D231.08
D231_MCB1_EE-: D231.07
D231_MCB1_F+: D231.14
D231_MCB1_F-: D231.13
D231_MCB1_FF+: D231.06
D231_MCB1_FF-: D231.05
D231_MCB1_G+: D231.12
D231_MCB1_G-: D231.11
D231_MCB1_GG+: D231.04
D231_MCB1_GG-: D231.03
D231_MCB1_H+: D231.10
D231_MCB1_H-: D231.09
D231_MCB1_HH+: D231.02
D231_MCB1_HH-: D231.01
D11616: D231.17 ; also on sheet 18
D12501: D125.01
D12502: D125.02
D12503: D125.03
D12504: D125.04
D12505: D125.05
D12506: D125.06
D12507: D125.07
D12508: D125.08
D12509: D125.09
D12510: D125.10
D12511: D125.11
D12512: D125.12
D12513: D125.13
D12514: D125.14
D12515: D125.15
D12516: D125.16
D12601: D126.01
D12602: D126.02
D12603: D126.03
D12604: D126.04
D12605: D126.05
D12606: D126.06
D12607: D126.07
D12608: D126.08
D12609: D126.09
D12610: D126.10
D12611: D126.11
D12612: D126.12
D12613: D126.13
D12614: D126.14
D12615: D126.15
D12616: D126.16
D12701: D127.01
D12702: D127.02
D12703: D127.03
D12704: D127.04
D12705: D127.05
D12706: D127.06
D12707: D127.07
D12708: D127.08
D12709: D127.09
D12710: D127.10
D12711: D127.11
D12712: D127.12
D12713: D127.13
D12714: D127.14
D12715: D127.15
D12716: D127.16
D12801: D128.01
D12802: D128.02
D12803: D128.03
D12804: D128.04
D12805: D128.05
D12806: D128.06
D12807: D128.07
D12808: D128.08
D12809: D128.09
D12810: D128.10
D12811: D128.11
D12812: D128.12
D12813: D128.13
D12814: D128.14
D12815: D128.15
D12816: D128.16
D12901: D129.01
D12902: D129.02
D12903: D129.03
D12904: D129.04
D12905: D129.05
D12906: D129.06
D12907: D129.07
D12908: D129.08
D12909: D129.09
D12910: D129.10
D12911: D129.11
D12912: D129.12
D12913: D129.13
D12914: D129.14
D12915: D129.15
D12916: D129.16
D13001: D130.01
D13002: D130.02
D13003: D130.03
D13004: D130.04
D13005: D130.05
D13006: D130.06
D13007: D130.07
D13008: D130.08
D13009: D130.09
D13010: D130.10
D13011: D130.11
D13012: D130.12
D13013: D130.13
D13014: D130.14
D13015: D130.15
D13016: D130.16
D13101: D131.01
D13102: D131.02
D13103: D131.03
D13104: D131.04
D13105: D131.05
D13106: D131.06
D13107: D131.07
D13108: D131.08
D13109: D131.09
D13110: D131.10
D13111: D131.11
D13112: D131.12
D13113: D131.13
D13114: D131.14
D13115: D131.15
D13116: D131.16
D13201: D132.01
D13202: D132.02
D13203: D132.03
D13204: D132.04
D13205: D132.05
D13206: D132.06
D13207: D132.07
D13208: D132.08
D13209: D132.09
D13210: D132.10
D13211: D132.11
D13212: D132.12
D13213: D132.13
D13214: D132.14
D13215: D132.15
D13216: D132.16
D20101: D201.01
D20102: D201.02
D20103: D201.03
D20104: D201.04
D20105: D201.05
D20106: D201.06
D20107: D201.07
D20108: D201.08
D20109: D201.09
D20110: D201.10
D20111: D201.11
D20112: D201.12
D20113: D201.13
D20114: D201.14
D20115: D201.15
D20116: D201.16
D20201: D202.01
D20202: D202.02
D20203: D202.03
D20204: D202.04
D20205: D202.05
D20206: D202.06
D20207: D202.07
D20208: D202.08
D20209: D202.09
D20210: D202.10
D20211: D202.11
D20212: D202.12
D20213: D202.13
D20214: D202.14
D20215: D202.15
D20216: D202.16
D20301: D203.01
D20302: D203.02
D20303: D203.03
D20304: D203.04
D20305: D203.05
D20306: D203.06
D20307: D203.07
D20308: D203.08
D20309: D203.09
D20310: D203.10
D20311: D203.11
D20312: D203.12
D20313: D203.13
D20314: D203.14
D20315: D203.15
D20316: D203.16
D20401: D204.01
D20402: D204.02
D20403: D204.03
D20404: D204.04
D20405: D204.05
D20406: D204.06
D20407: D204.07
D20408: D204.08
D20409: D204.09
D20410: D204.10
D20411: D204.11
D20412: D204.12
D20413: D204.13
D20414: D204.14
D20415: D204.15
D20416: D204.16
D20501: D205.01
D20502: D205.02
D20503: D205.03
D20504: D205.04
D20505: D205.05
D20506: D205.06
D20507: D205.07
D20508: D205.08
D20509: D205.09
D20510: D205.10
D20511: D205.11
D20512: D205.12
D20513: D205.13
D20514: D205.14
D20515: D205.15
D20516: D205.16
D20601: D206.01
D20602: D206.02
D20603: D206.03
D20604: D206.04
D20605: D206.05
D20606: D206.06
D20607: D206.07
D20608: D206.08
D20609: D206.09
D20610: D206.10
D20611: D206.11
D20612: D206.12
D20613: D206.13
D20614: D206.14
D20615: D206.15
D20616: D206.16
D20701: D207.01
D20702: D207.02
D20703: D207.03
D20704: D207.04
D20705: D207.05
D20706: D207.06
D20707: D207.07
D20708: D207.08
D20709: D207.09
D20710: D207.10
D20711: D207.11
D20712: D207.12
D20713: D207.13
D20714: D207.14
D20715: D207.15
D20716: D207.16
D20801: D208.01
D20802: D208.02
D20803: D208.03
D20804: D208.04
D20805: D208.05
D20806: D208.06
D20807: D208.07
D20808: D208.08
D20809: D208.09
D20810: D208.10
D20811: D208.11
D20812: D208.12
D20813: D208.13
D20814: D208.14
D20815: D208.15
D20816: D208.16
D20901: D209.01
D20902: D209.02
D20903: D209.03
D20904: D209.04
D20905: D209.05
D20906: D209.06
D20907: D209.07
D20908: D209.08
D20909: D209.09
D20910: D209.10
D20911: D209.11
D20912: D209.12
D20913: D209.13
D20914: D209.14
D20915: D209.15
D20916: D209.16
D21001: D210.01
D21002: D210.02
D21003: D210.03
D21004: D210.04
D21005: D210.05
D21006: D210.06
D21007: D210.07
D21008: D210.08
D21009: D210.09
D21010: D210.10
D21011: D210.11
D21012: D210.12
D21013: D210.13
D21014: D210.14
D21015: D210.15
D21016: D210.16
D21101: D211.01
D21102: D211.02
D21103: D211.03
D21104: D211.04
D21105: D211.05
D21106: D211.06
D21107: D211.07
D21108: D211.08
D21109: D211.09
D21110: D211.10
D21111: D211.11
D21112: D211.12
D21113: D211.13
D21114: D211.14
D21115: D211.15
D21116: D211.16
D21201: D212.01
D21202: D212.02
D21203: D212.03
D21204: D212.04
D21205: D212.05
D21206: D212.06
D21207: D212.07
D21208: D212.08
D21209: D212.09
D21210: D212.10
D21211: D212.11
D21212: D212.12
D21213: D212.13
D21214: D212.14
D21215: D212.15
D21216: D212.16
D21301: D213.01
D21302: D213.02
D21303: D213.03
D21304: D213.04
D21305: D213.05
D21306: D213.06
D21307: D213.07
D21308: D213.08
D21309: D213.09
D21310: D213.10
D21311: D213.11
D21312: D213.12
D21313: D213.13
D21314: D213.14
D21315: D213.15
D21316: D213.16
D21401: D214.01
D21402: D214.02
D21403: D214.03
D21404: D214.04
D21405: D214.05
D21406: D214.06
D21407: D214.07
D21408: D214.08
D21409: D214.09
D21410: D214.10
D21411: D214.11
D21412: D214.12
D21413: D214.13
D21414: D214.14
D21415: D214.15
D21416: D214.16
D21501: D215.01
D21502: D215.02
D21503: D215.03
D21504: D215.04
D21505: D215.05
D21506: D215.06
D21507: D215.07
D21508: D215.08
D21509: D215.09
D21510: D215.10
D21511: D215.11
D21512: D215.12
D21513: D215.13
D21514: D215.14
D21515: D215.15
D21516: D215.16
D21601: D216.01
D21602: D216.02
D21603: D216.03
D21604: D216.04
D21605: D216.05
D21606: D216.06
D21607: D216.07
D21608: D216.08
D21609: D216.09
D21610: D216.10
D21611: D216.11
D21612: D216.12
D21613: D216.13
D21614: D216.14
D21615: D216.15
D21616: D216.16
D21701: D217.01
D21702: D217.02
D21703: D217.03
D21704: D217.04
D21705: D217.05
D21706: D217.06
D21707: D217.07
D21708: D217.08
D21709: D217.09
D21710: D217.10
D21711: D217.11
D21712: D217.12
D21713: D217.13
D21714: D217.14
D21715: D217.15
D21716: D217.16
D21801: D218.01
D21802: D218.02
D21803: D218.03
D21804: D218.04
D21805: D218.05
D21806: D218.06
D21807: D218.07
D21808: D218.08
D21809: D218.09
D21810: D218.10
D21811: D218.11
D21812: D218.12
D21813: D218.13
D21814: D218.14
D21815: D218.15
D21816: D218.16
D21901: D219.01
D21902: D219.02
D21903: D219.03
D21904: D219.04
D21905: D219.05
D21906: D219.06
D21907: D219.07
D21908: D219.08
D21909: D219.09
D21910: D219.10
D21911: D219.11
D21912: D219.12
D21913: D219.13
D21914: D219.14
D21915: D219.15
D21916: D219.16
D22001: D220.01
D22002: D220.02
D22003: D220.03
D22004: D220.04
D22005: D220.05
D22006: D220.06
D22007: D220.07
D22008: D220.08
D22009: D220.09
D22010: D220.10
D22011: D220.11
D22012: D220.12
D22013: D220.13
D22014: D220.14
D22015: D220.15
D22016: D220.16
D22101: D221.01
D22102: D221.02
D22103: D221.03
D22104: D221.04
D22105: D221.05
D22106: D221.06
D22107: D221.07
D22108: D221.08
D22109: D221.09
D22110: D221.10
D22111: D221.11
D22112: D221.12
D22113: D221.13
D22114: D221.14
D22115: D221.15
D22116: D221.16
D22201: D222.01
D22202: D222.02
D22203: D222.03
D22204: D222.04
D22205: D222.05
D22206: D222.06
D22207: D222.07
D22208: D222.08
D22209: D222.09
D22210: D222.10
D22211: D222.11
D22212: D222.12
D22213: D222.13
D22214: D222.14
D22215: D222.15
D22216: D222.16
D22301: D223.01
D22302: D223.02
D22303: D223.03
D22304: D223.04
D22305: D223.05
D22306: D223.06
D22307: D223.07
D22308: D223.08
D22309: D223.09
D22310: D223.10
D22311: D223.11
D22312: D223.12
D22313: D223.13
D22314: D223.14
D22315: D223.15
D22316: D223.16
D22401: D224.01
D22402: D224.02
D22403: D224.03
D22404: D224.04
D22405: D224.05
D22406: D224.06
D22407: D224.07
D22408: D224.08
D22409: D224.09
D22410: D224.10
D22411: D224.11
D22412: D224.12
D22413: D224.13
D22414: D224.14
D22415: D224.15
D22416: D224.16
DPS8_C1: DPS8.C01
DPS8_C5: DPS8.C05
DPS8_C11: DPS8.C11
DPS8_C15: DPS8.C15
MSDPS1_TR+: DPS8.A09 ; also on sheet 16 17 18 19
MSDPS1_VB+: DPS8.C09 ; also on sheet 16 17 18 19
MSDPS8_1F: DPS8.C03
MSDPS8_1GRD: DPS8.B02
MSDPS8_1GS: DPS8.A02
MSDPS8_1S: DPS8.C02
MSDPS8_2F: DPS8.C07
MSDPS8_2GRD: DPS8.B06
MSDPS8_2GS: DPS8.A06
MSDPS8_2S: DPS8.C06
MSDPS8_3F: DPS8.C13
MSDPS8_3GRD: DPS8.B12
MSDPS8_3GS: DPS8.A12
MSDPS8_3S: DPS8.C12
MSDPS8_4F: DPS8.C17
MSDPS8_4GRD: DPS8.B16
MSDPS8_4GS: DPS8.A16
MSDPS8_4S: DPS8.C16
MSDPS8_5F: DPS8.A03
MSDPS8_5GS: DPS8.B01
MSDPS8_5S: DPS8.B03
MSDPS8_6F: DPS8.A07
MSDPS8_6GS: DPS8.B05
MSDPS8_6S: DPS8.B07
MSDPS8_7F: DPS8.A13
MSDPS8_7GS: DPS8.B11
MSDPS8_7S: DPS8.B13
MSDPS8_8F: DPS8.A17
MSDPS8_8GS: DPS8.B15
MSDPS8_8S: DPS8.B17
MSDPS8_TRVB-: DPS8.B09 SB8.2
UDBGND: CB7.2 CB8.1 CB9.2 CB10.2 CB11.2 CB12.2 CB13.2 CB14.2 CB15.2 CB16.2 UTL4.A02 UTL4.A08 UTL4.A10 UTL4.A12 UTL4.A14 UTL4.B01 UTL4.B07 UTL4.B09 UTL4.B11 UTL4.B13 UTL5.A02 UTL5.A08 UTL5.A10 UTL5.A12 UTL5.A14 UTL5.B01 UTL5.B07 UTL5.B09 UTL5.B11 UTL5.B13 UTL6.A02 UTL6.A08 UTL6.A10 UTL6.A12 UTL6.A14 UTL6.B01 UTL6.B07 UTL6.B09 UTL6.B11 UTL6.B13 UTL7.A02 UTL7.A08 UTL7.A10 UTL7.A12 UTL7.A14 UTL7.B01 UTL7.B07 UTL7.B09 UTL7.B11 UTL7.B13 UTL8.A02 UTL8.A08 UTL8.A10 UTL8.A12 UTL8.A14 UTL8.B01 UTL8.B07 UTL8.B09 UTL8.B11 UTL8.B13 ; also on sheet 16 17 18 19
UT1_UP5V: CB7.1 CB8.2 CB9.1 CB10.1 CB11.1 CB12.1 CB13.1 CB14.1 CB15.1 CB16.1 UTL4.A05 UTL4.B04 UTL5.A05 UTL5.B04 UTL6.A05 UTL6.B04 UTL7.A05 UTL7.B04 UTL8.A05 UTL8.B04 ; also on sheet 1 2 3 4 5 6 7 8 9 12 13 14 16 17 18 19
UT4_PDCF: UTL4.B15
UT4_PDCS: UTL4.A15
UT4_PGDS: UTL4.A16
UT4_PGRD: UTL4.B16
UT4_URW00: UTL4.A01
UT4_URW01: UTL4.B02
UT4_URW02: UTL4.A03
UT4_URW03: UTL4.B03
UT4_URW04: UTL4.A04
UT4_URW05: UTL4.B05
UT4_URW06: UTL4.A06
UT4_UW07: UTL4.B06
UT4_UW08: UTL4.A07
UT4_UW09: UTL4.B08
UT4_UW10: UTL4.A09
UT4_UW11: UTL4.B10
UT4_UW12: UTL4.A11
UT4_UW13: UTL4.B12
UT4_UW14: UTL4.A13
UT4_UW15: UTL4.B14
UT5_PDCF: UTL5.B15
UT5_PDCS: UTL5.A15
UT5_PGDS: UTL5.A16
UT5_PGRD: UTL5.B16
UT5_UW00: UTL5.A01
UT5_UW01: UTL5.B02
UT5_UW02: UTL5.A03
UT5_UW03: UTL5.B03
UT5_UW04: UTL5.A04
UT5_UW05: UTL5.B05
UT5_UW06: UTL5.A06
UT5_UW07: UTL5.B06
UT5_UW08: UTL5.A07
UT5_UW09: UTL5.B08
UT5_UW10: UTL5.A09
UT5_UW11: UTL5.B10
UT5_UW12: UTL5.A11
UT5_UW13: UTL5.B12
UT5_UW14: UTL5.A13
UT5_UW15: UTL5.B14
UT6_PDCF: UTL6.B15
UT6_PDCS: UTL6.A15
UT6_PGDS: UTL6.A16
UT6_PGRD: UTL6.B16
UT6_UW00: UTL6.A01
UT6_UW01: UTL6.B02
UT6_UW02: UTL6.A03
UT6_UW03: UTL6.B03
UT6_UW04: UTL6.A04
UT6_UW05: UTL6.B05
UT6_UW06: UTL6.A06
UT6_UW07: UTL6.B06
UT6_UW08: UTL6.A07
UT6_UW09: UTL6.B08
UT6_UW10: UTL6.A09
UT6_UW11: UTL6.B10
UT6_UW12: UTL6.A11
UT6_UW13: UTL6.B12
UT6_UW14: UTL6.A13
UT6_UW15: UTL6.B14
UT7_PDCF: UTL7.B15
UT7_PDCS: UTL7.A15
UT7_PGDS: UTL7.A16
UT7_PGRD: UTL7.B16
UT7_UW00: UTL7.A01
UT7_UW01: UTL7.B02
UT7_UW02: UTL7.A03
UT7_UW03: UTL7.B03
UT7_UW04: UTL7.A04
UT7_UW05: UTL7.B05
UT7_UW06: UTL7.A06
UT7_UW07: UTL7.B06
UT7_UW08: UTL7.A07
UT7_UW09: UTL7.B08
UT7_UW10: UTL7.A09
UT7_UW11: UTL7.B10
UT7_UW12: UTL7.A11
UT7_UW13: UTL7.B12
UT7_UW14: UTL7.A13
UT7_UW15: UTL7.B14
UT8_PDCF: UTL8.B15
UT8_PDCS: UTL8.A15
UT8_PGDS: UTL8.A16
UT8_PGRD: UTL8.B16
UT8_UW00: UTL8.A01
UT8_UW01: UTL8.B02
UT8_UW02: UTL8.A03
UT8_UW03: UTL8.B03
UT8_UW04: UTL8.A04
UT8_UW05: UTL8.B05
UT8_UW06: UTL8.A06
UT8_UW07: UTL8.B06
UT8_UW08: UTL8.A07
UT8_UW09: UTL8.B08
UT8_UW10: UTL8.A09
UT8_UW11: UTL8.B10
UT8_UW12: UTL8.A11
UT8_UW13: UTL8.B12
UT8_UW14: UTL8.A13
UT8_UW15: UTL8.B14

Not connected (* = marked no-connect by the designer): CSDPS225 A17* B17* C17* D17*; CSDPS229 A17* B17* C17* D17*; CSDPS425 A17* B17* C17* D17*; CSDPS429 A17* B17* C17* D17*; D125 17* A17* B17*; D126 17* A17* B17*; D127 17* A17* B17*; D128 17* A17* B17*; D129 17* A17* B17*; D130 17* A17* B17*; D131 17* A17* B17*; D132 17* A17* B17*; D201 17* A17* B17*; D202 17* A17* B17*; D203 17* A17* B17*; D204 17* A17* B17*; D205 17* A17* B17*; D206 17* A17* B17*; D207 17* A17* B17*; D208 17* A17* B17*; D209 17* A17* B17*; D210 17* A17* B17*; D211 17* A17* B17*; D212 17* A17* B17*; D213 17* A17* B17*; D214 17* A17* B17*; D215 17* A17* B17*; D216 17* A17* B17*; D217 17* A17* B17*; D218 17* A17* B17*; D219 17* A17* B17*; D220 17* A17* B17*; D221 17* A17* B17*; D222 17* A17* B17*; D223 17* A17* B17*; D224 17* A17* B17*; D431 01 02 03 04 05 06 07 08 09 10 11 12 13 14 15 16 17; DPS4 A02* A03* A04* A06* A07* A08* A09* A10* A12* A13* A14* A16* A17* B01* B02* B03* B04* B05* B06* B07* B08* B09* B10* B11* B12* B13* B14* B15* B16* B17* C02* C03* C04* C06* C07* C08* C09* C10* C12* C13* C14* C16* C17*; DPS5 A02* A03* A04* A06* A07* A08* A09* A10* A12* A13* A14* A16* A17* B01* B02* B03* B04* B05* B06* B07* B08* B09* B10* B11* B12* B13* B14* B15* B16* B17* C02* C03* C04* C06* C07* C08* C09* C10* C12* C13* C14* C16* C17*; DPS8 A04* A08* A10* A14* B04* B08* B10* B14* C04* C08* C10* C14*; FD1 1(FD)*; FD2 1(FD)*; FD3 1(FD)*; FD4 1(FD)*; FD5 1(FD)*; FD6 1(FD)*; FD7 1(FD)*; FD8 1(FD)*; FD9 1(FD)*; FD10 1(FD)*; FD11 1(FD)*; FD12 1(FD)*; FD13 1(FD)*; FD14 1(FD)*; FD15 1(FD)*; FD16 1(FD)*; SKB1 NUT1* NUT2* NUT3* NUT4*; TPL1 1(TP)*; TPL2 1(TP)*; TPL3 1(TP)*; TPL4 1(TP)*; TPL5 1(TP)*; TPL6 1(TP)*; TPL7 1(TP)*; TPL8 1(TP)*; TPL9 1(TP)*; TPL10 1(TP)*; TPL11 1(TP)*; TPL12 1(TP)*; TPL13 1(TP)*; TPL14 1(TP)*; TPL15 1(TP)*; TPL16 1(TP)*; UTL4 A17* B17*; UTL5 A17* B17*; UTL6 A17* B17*; UTL7 A17* B17*; UTL8 A17* B17*

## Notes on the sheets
sheet 20
- GROUP8
- VI32
- VI32
- PS RF FE1
- PS RF FE2
- MCB S/M1
- MCB S/M1
- MCB S/M2
- MCB S/M2
- D229
- D429
- D230
- D430
- D231
- D431
- D232
- D432
- GPDPS:GND
- GPDPS:FORCE
- GPDPS:FORCE
- GPDPS:GND
- GPDPS:FORCE
- GPDPS:FORCE
- GPDPS:GND
- GPDPS:FORCE
- GPDPS:FORCE
- GPDPS:GND
- GPDPS:FORCE
- GPDPS:FORCE
- Half Size : WGD is in slot 430
- D231:¬°CAPTURE
- D431:¬°SOURCE+CAPTURE
- E.F.G.H¸û±`¨Ï¥Î
- A.B.C.D¸û±`¨Ï¥Î
- 3/4 Size  : WGD is in slot 230
- EE.FF.GG.HH¬°MCB(MBAV8)¤~¦³
- AA.BB.CC.DD¬°MCB(MBAV8)¤~¦³
- PS RF SRC-1-2
- DPS32
- DPS32
- MCC
- MCC
- PS RF SRC-3-4
- MCB M/M
- MCB M/M
- D225
- D425
- D226
- D426
- D227
- D427
- D228
- D428
- V93000 GROUP1
- VY22520
sheet 21
- GROUP4
- D129
- D329
- D130
- D330
- D131
- D331
- D132
- D332
- D125
- D325
- D126
- D326
- D127
- D327
- D128
- D328
sheet 22
- GROUP5
- D205
- D405
- D206
- D406
- D207
- D407
- D208
- D408
- D201
- D401
- D202
- D402
- D203
- D403
- D204
- D404
- MT6253
sheet 23
- GROUP6
- D213
- D413
- D214
- D414
- D215
- D415
- D216
- D416
- D209
- D409
- D210
- D410
- D211
- D411
- D212
- D412
sheet 24
- GROUP7
- D221
- D421
- D222
- D422
- D223
- D423
- D224
- D424
- D217
- D417
- D218
- D418
- D219
- D419
- D220
- D420
sheet 25
- Assign Rule
- SITE1
- SITE2
- SITE3
- SITE4
- SHARE
- TOTAL
- 41
- 41
- 41
- 41
- 4
- 168
- ASSIGN TO PS1600 (D103, D104, D107~D124
- S*_DCH*
- DO NOT USE D101, D102, D105, D106
- 4
- 4
- 4
- 4
- 0
- 16
- ASSIGN TO PS1600 (D103, D104, D107~D124
- DIFF 100 OHM
- S*_AUX_100DCH*
- DO NOT USE D101, D102, D105, D106
- S*_RX_85DCH*
- 8
- 8
- 8
- 8
- 0
- 32
- Assign to PS9G (D301, D305, D302, D306),keeping them as short as possible and equal in length
- Same site must be the same SLOT.
- DIFF 85 OHM
- 16
- 16
- 16
- 16
- 0
- 64
- Assign to PS9G (D301, D305, D302, D306), keeping them as short as possible and equal in length
- S*_TX_100DCH*
- Same site must be the same SLOT.
- DIFF 100 OHM
- S*_DPS*
- 13+1(MERGE)
- 13+1(MERGE)
- 13+1(MERGE)
- 13+1(MERGE)
- 0
- 56
- Assign to CSDPS (D225, D425, D229, D429) and merge 2 groups
- Merge rule : Odd, Odd + 1
- 16
- 16
- 16
- 16
- 2
- 66
- ASSIGN TO UT1~UT8
- S*_RLY*
- 1.DIGITAL TOTAL: (168+16)=184. Designated : D12411, D12410, D11615, D11616.
- 2.POWER TOTAL:56,USE CSDPS
- 3.REALY TOTAL:66,Designated UT1_UW14,UT1_UW15
- 4.PS9G TOTAL:32+64=96
- 5.PS9G Assign rule
  Assign:D301,D302,D305,D306¡FKeep the slot identical for the same site,DIFF 100 OHM , T-hole
- 6.93K DIFF Assign rule
  0103¡B0204¡B0507¡B0608¡B0911¡B1012¡B1315¡B1416
- Needs to be  vertical drilling on the Base Pogo
- SOCKET BASE
- FD MARK
- Threading holes, 4 per site
